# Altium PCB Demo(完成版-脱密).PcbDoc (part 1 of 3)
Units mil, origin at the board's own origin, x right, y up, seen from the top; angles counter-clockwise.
Board outline 2165.35 x 1574.8 mil, 6 copper layers (TOP, GND02, ART03, ART04, PWR05, BOTTOM); 172 components, 0 nets, 834 pads, 541 vias.
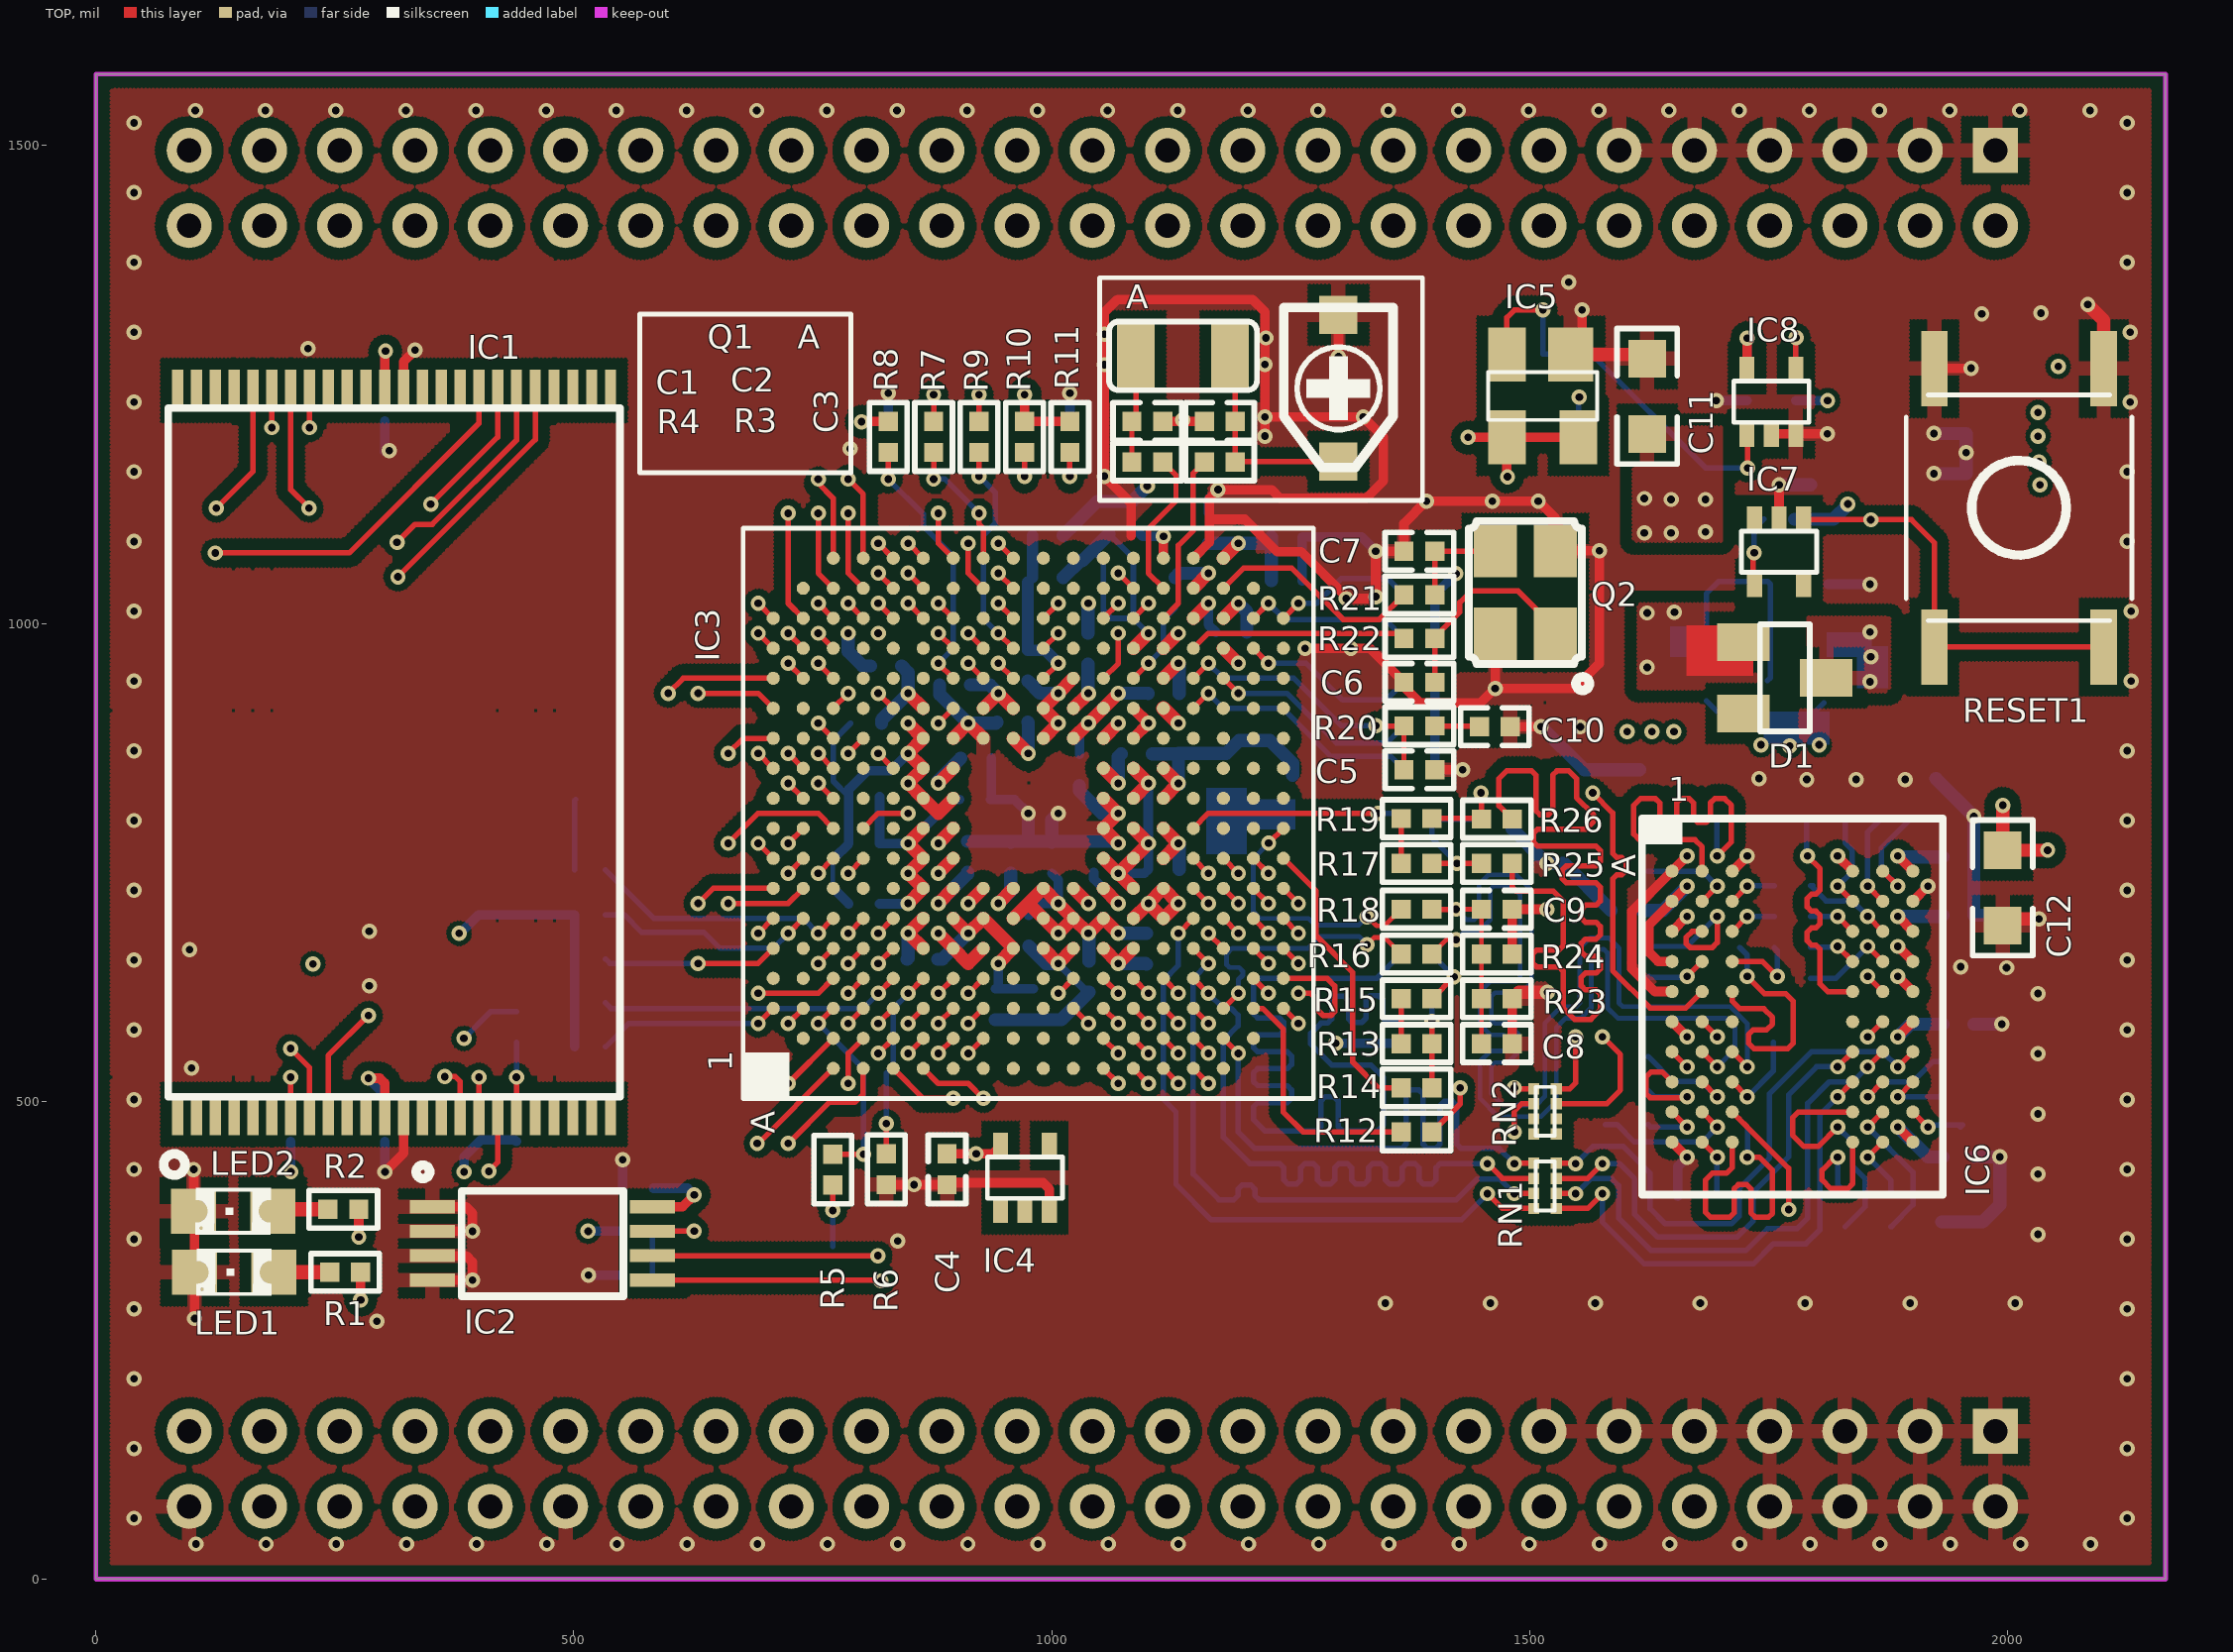
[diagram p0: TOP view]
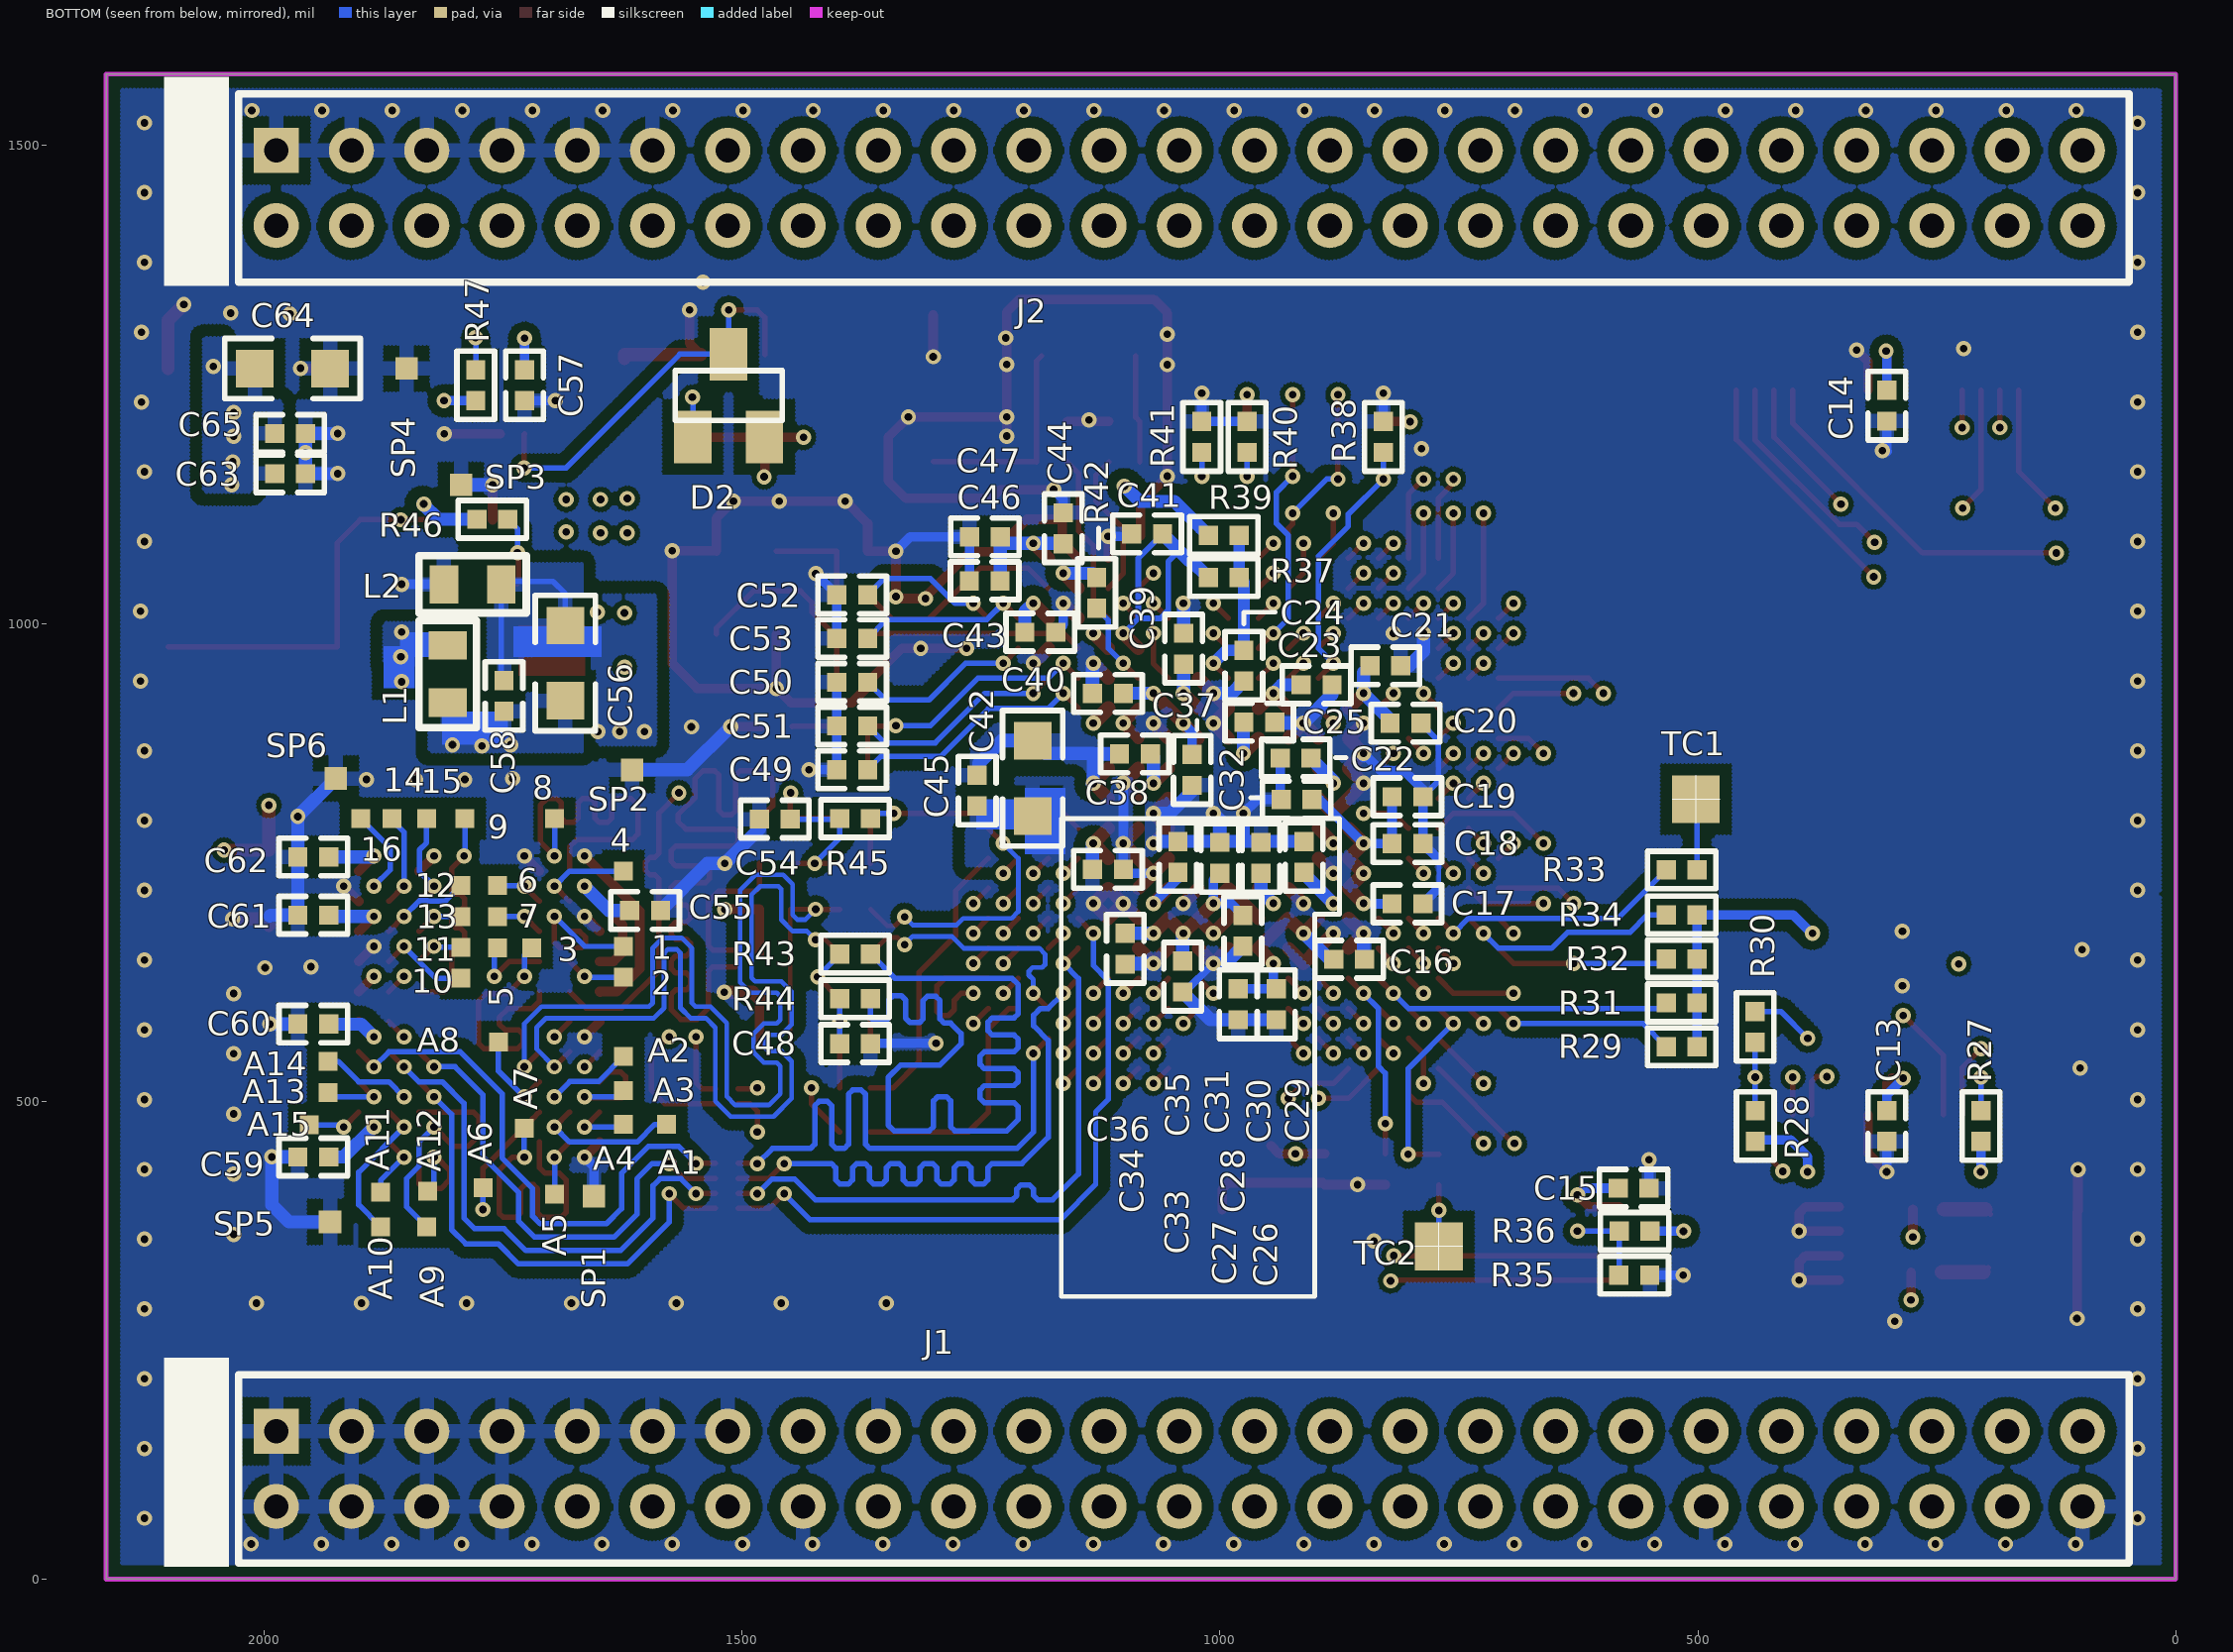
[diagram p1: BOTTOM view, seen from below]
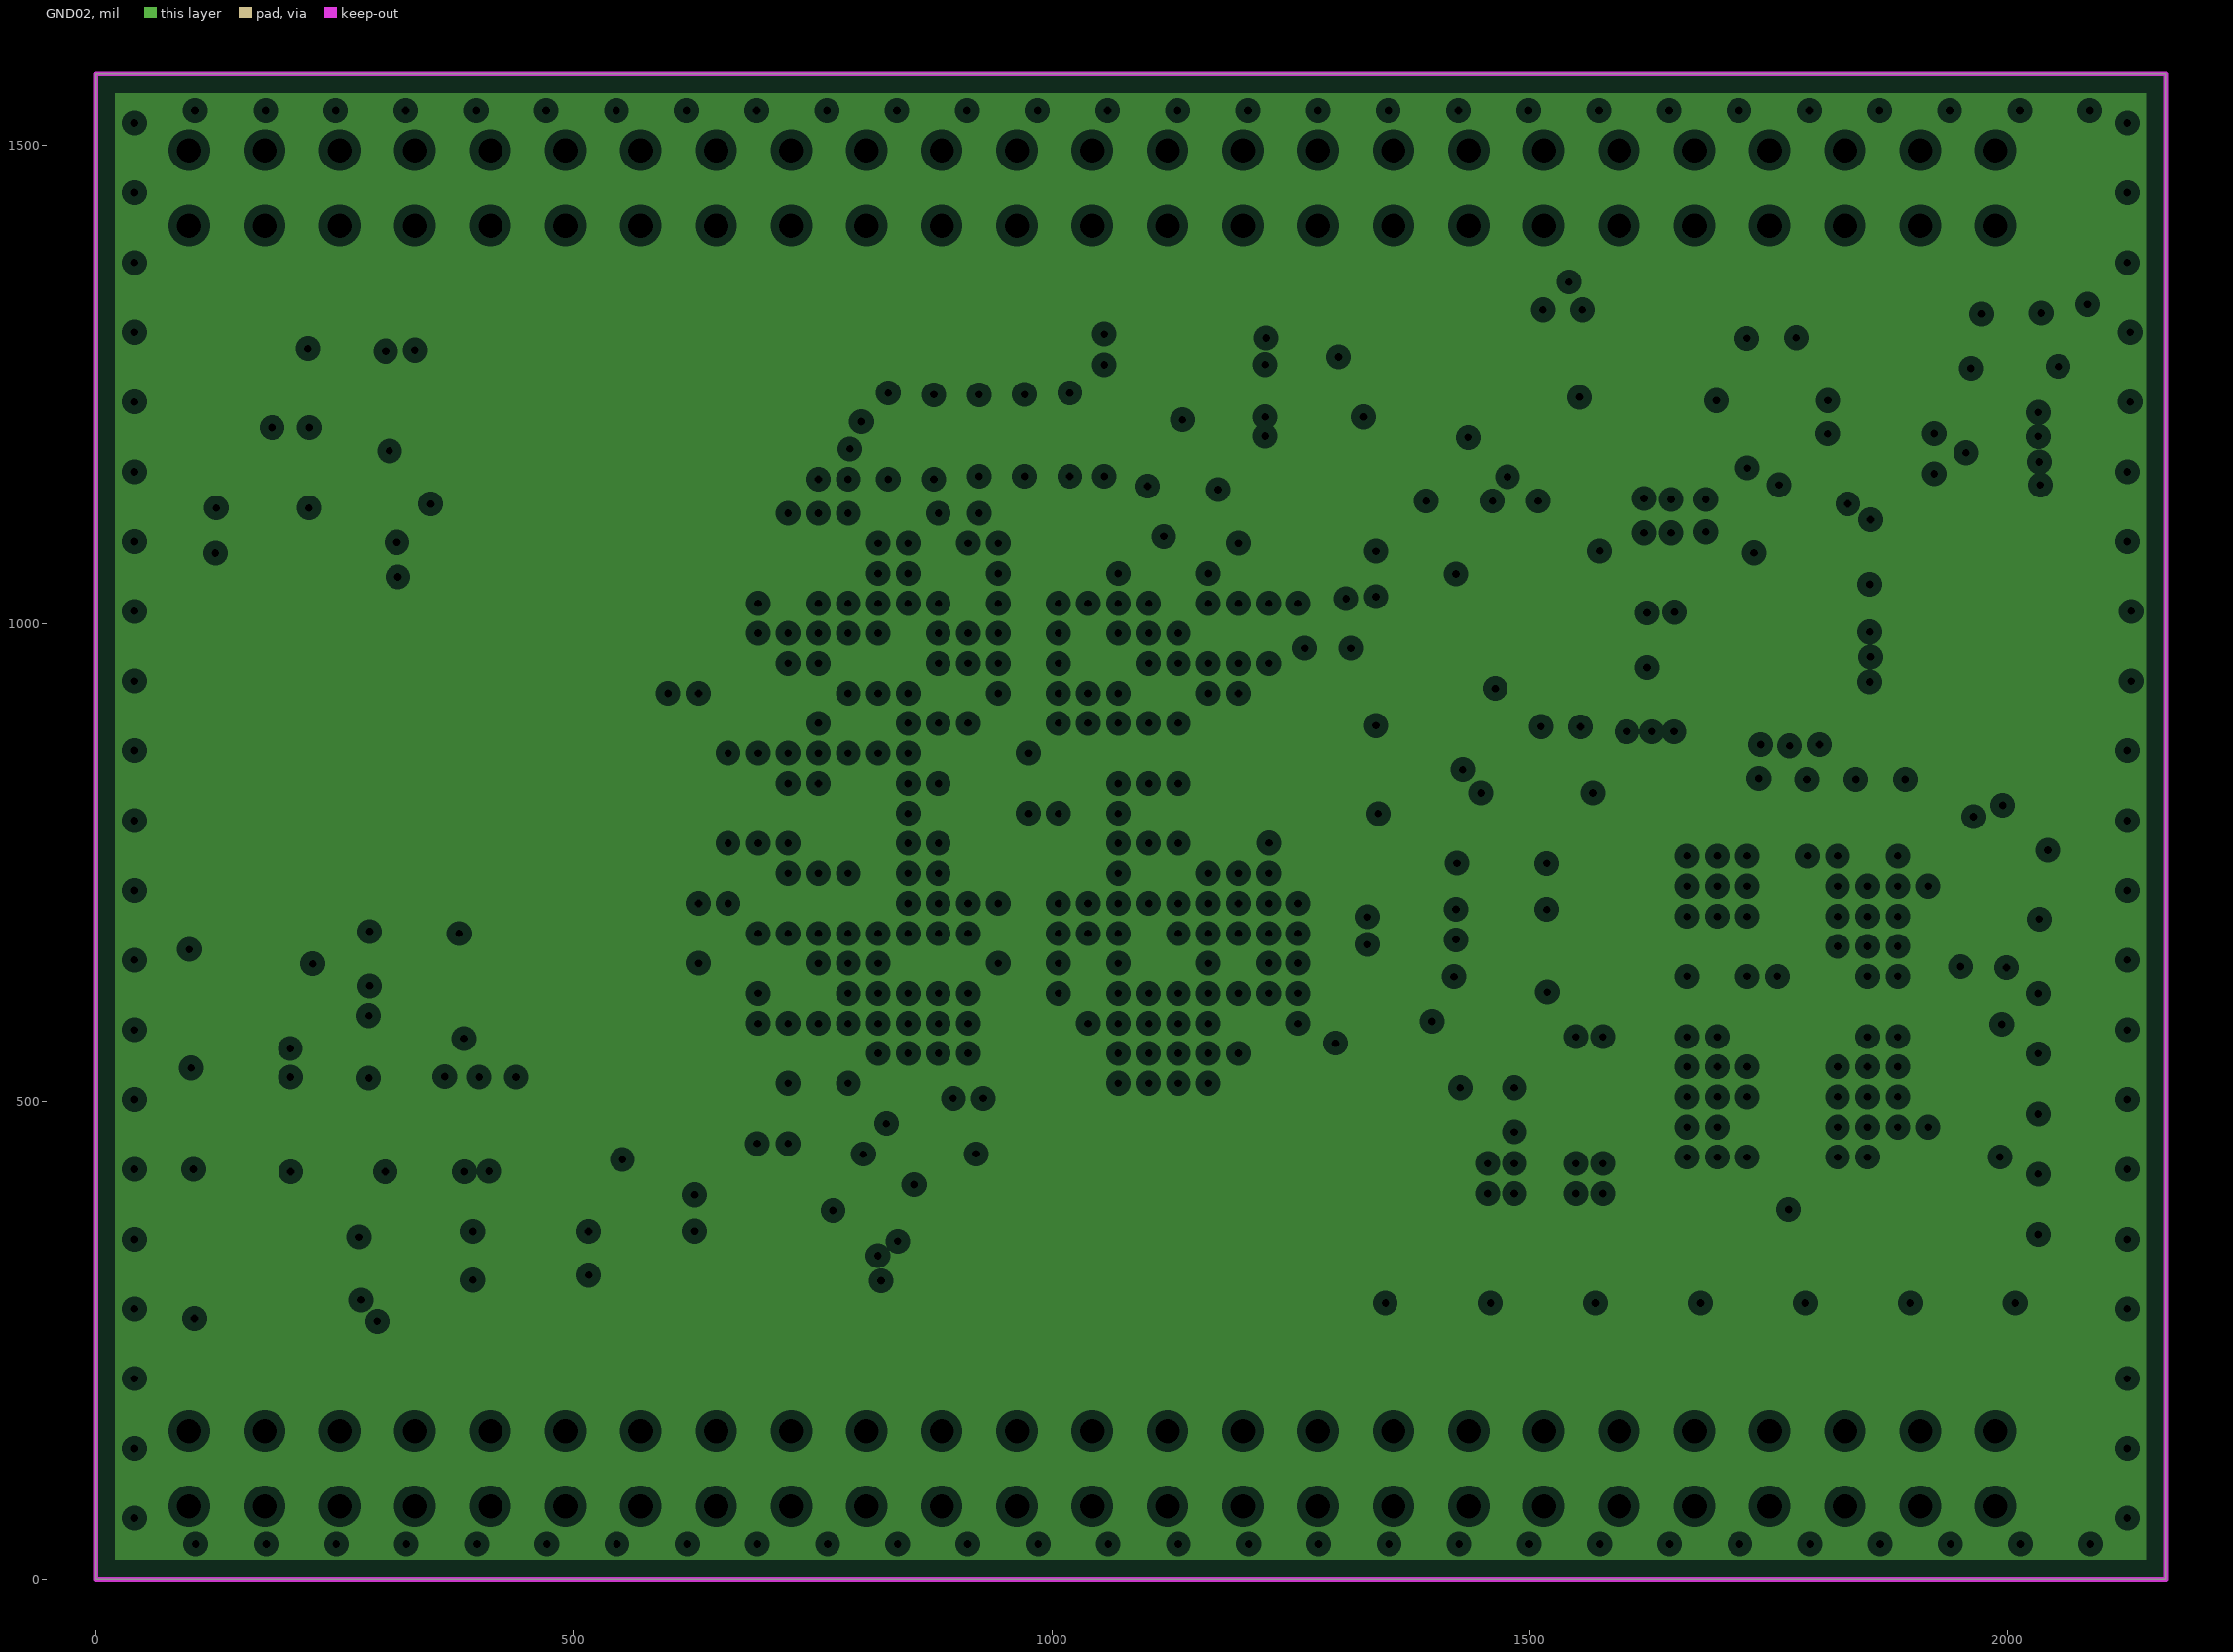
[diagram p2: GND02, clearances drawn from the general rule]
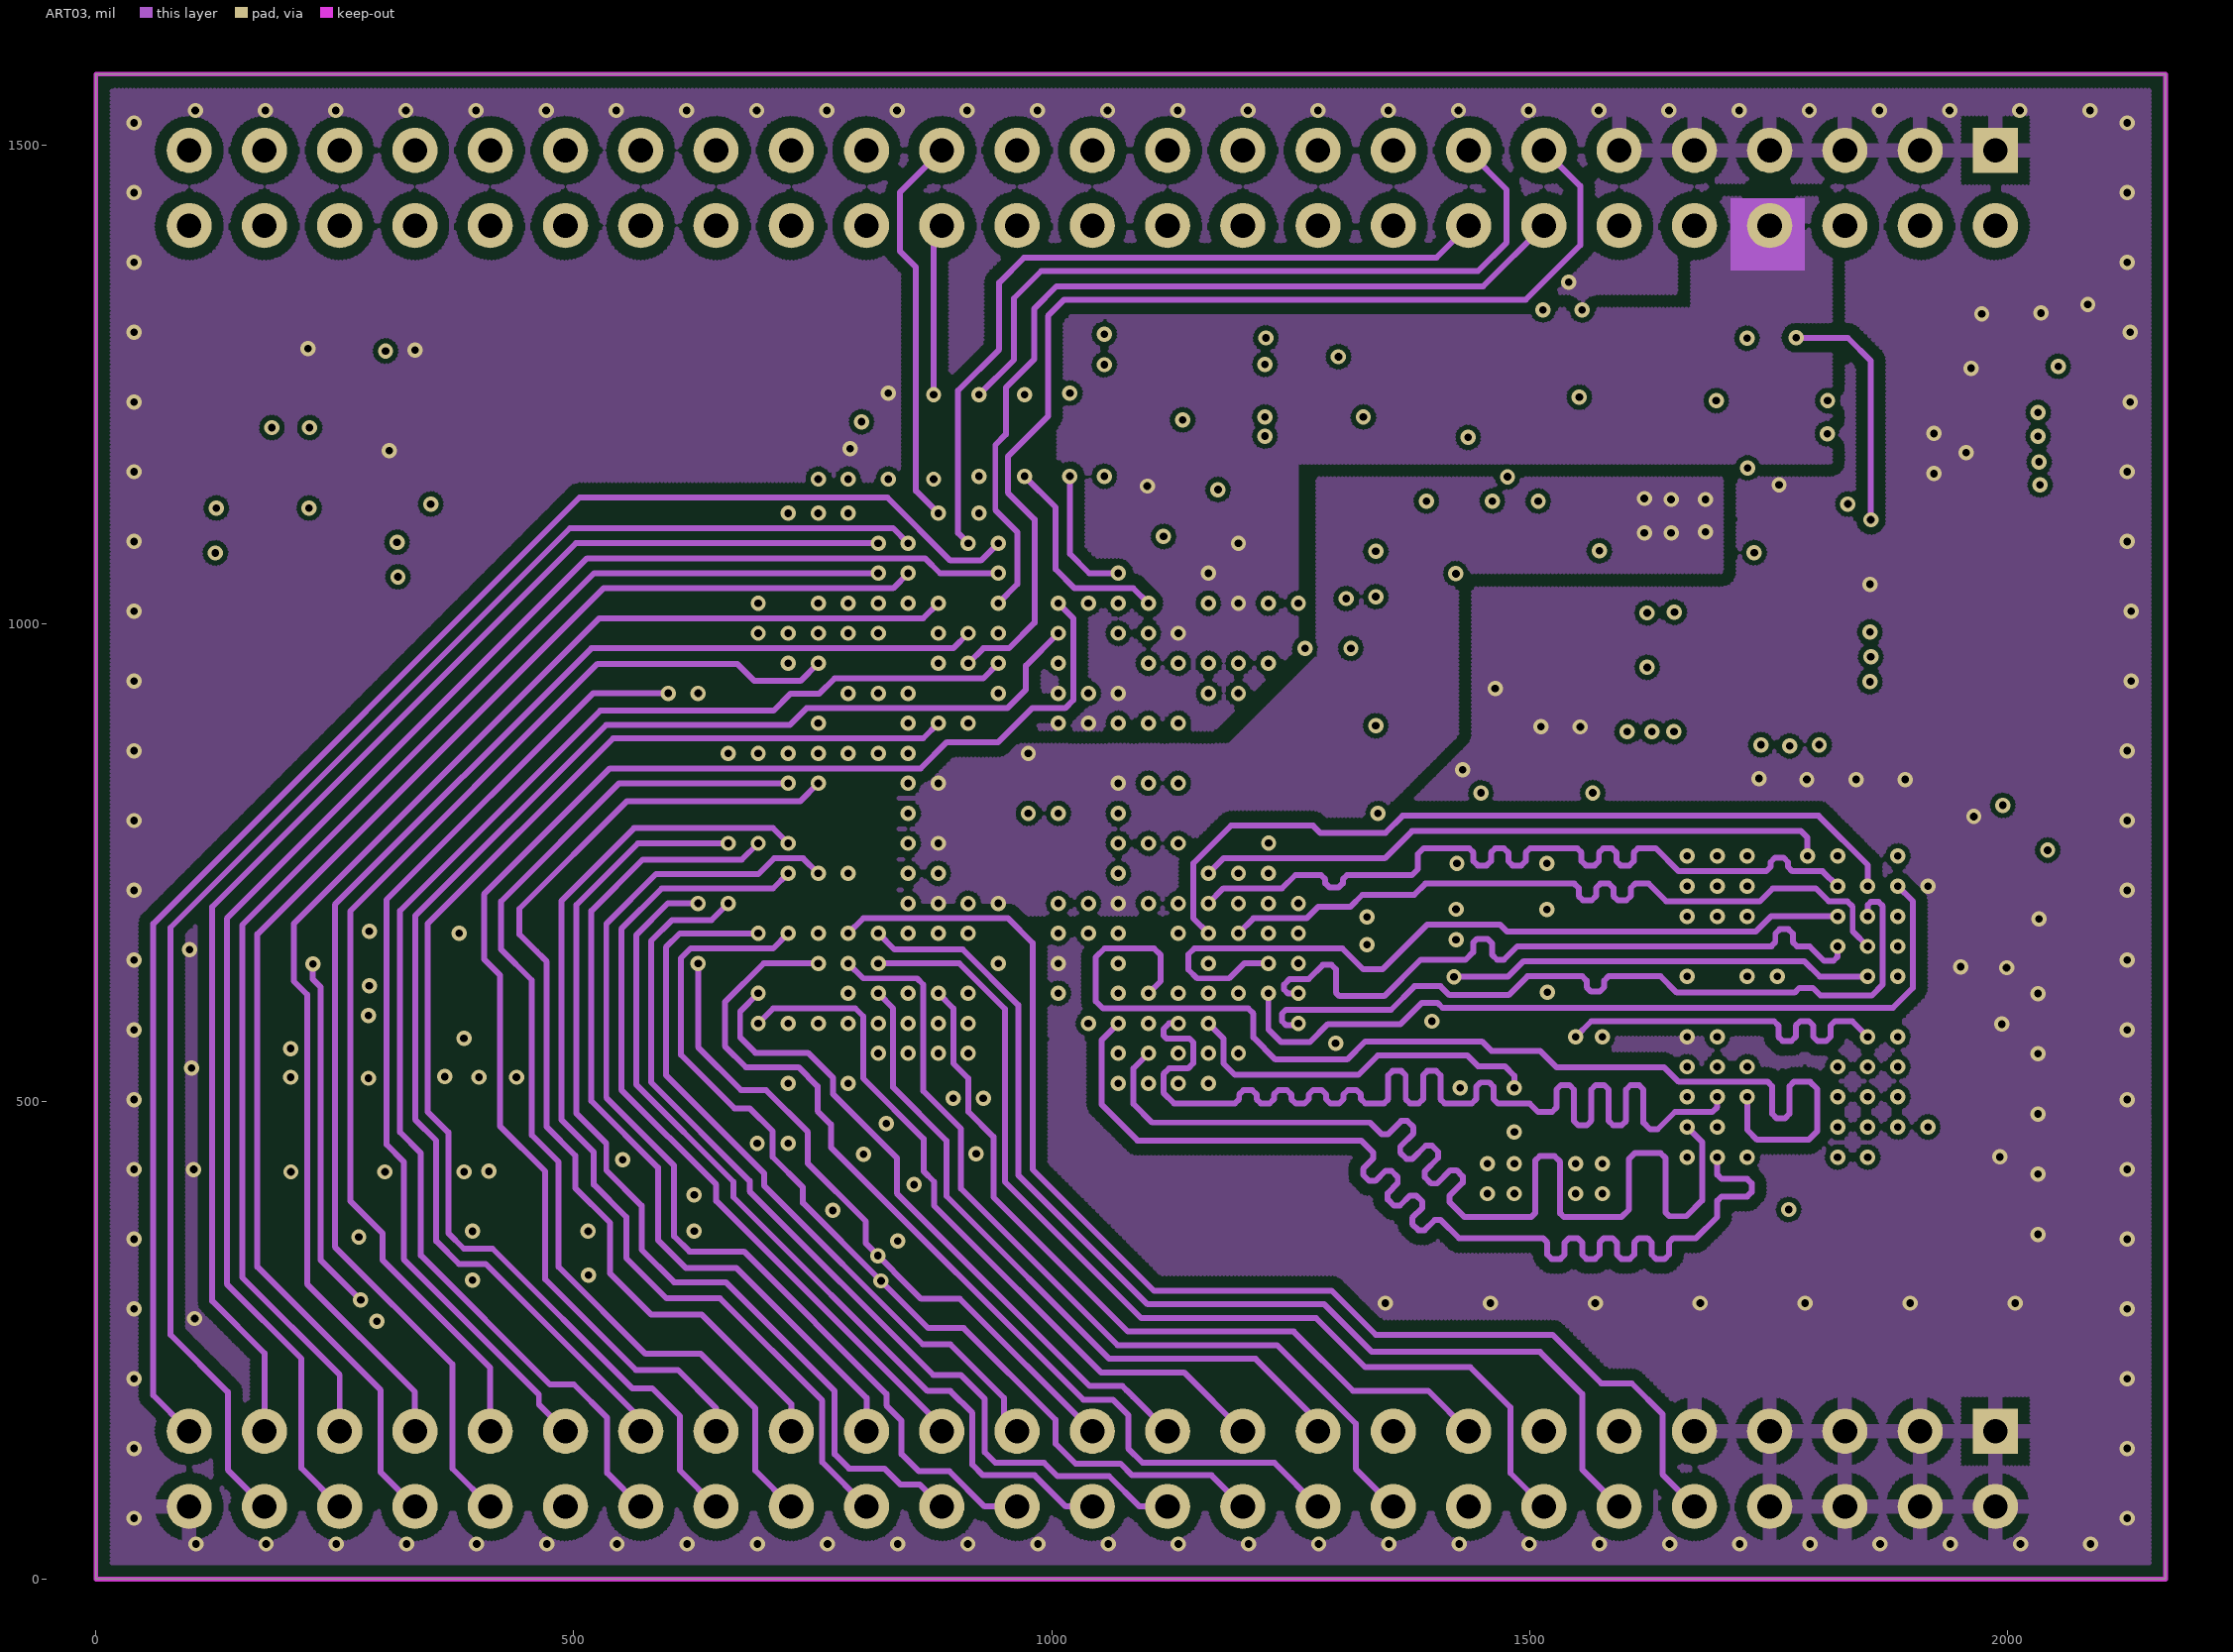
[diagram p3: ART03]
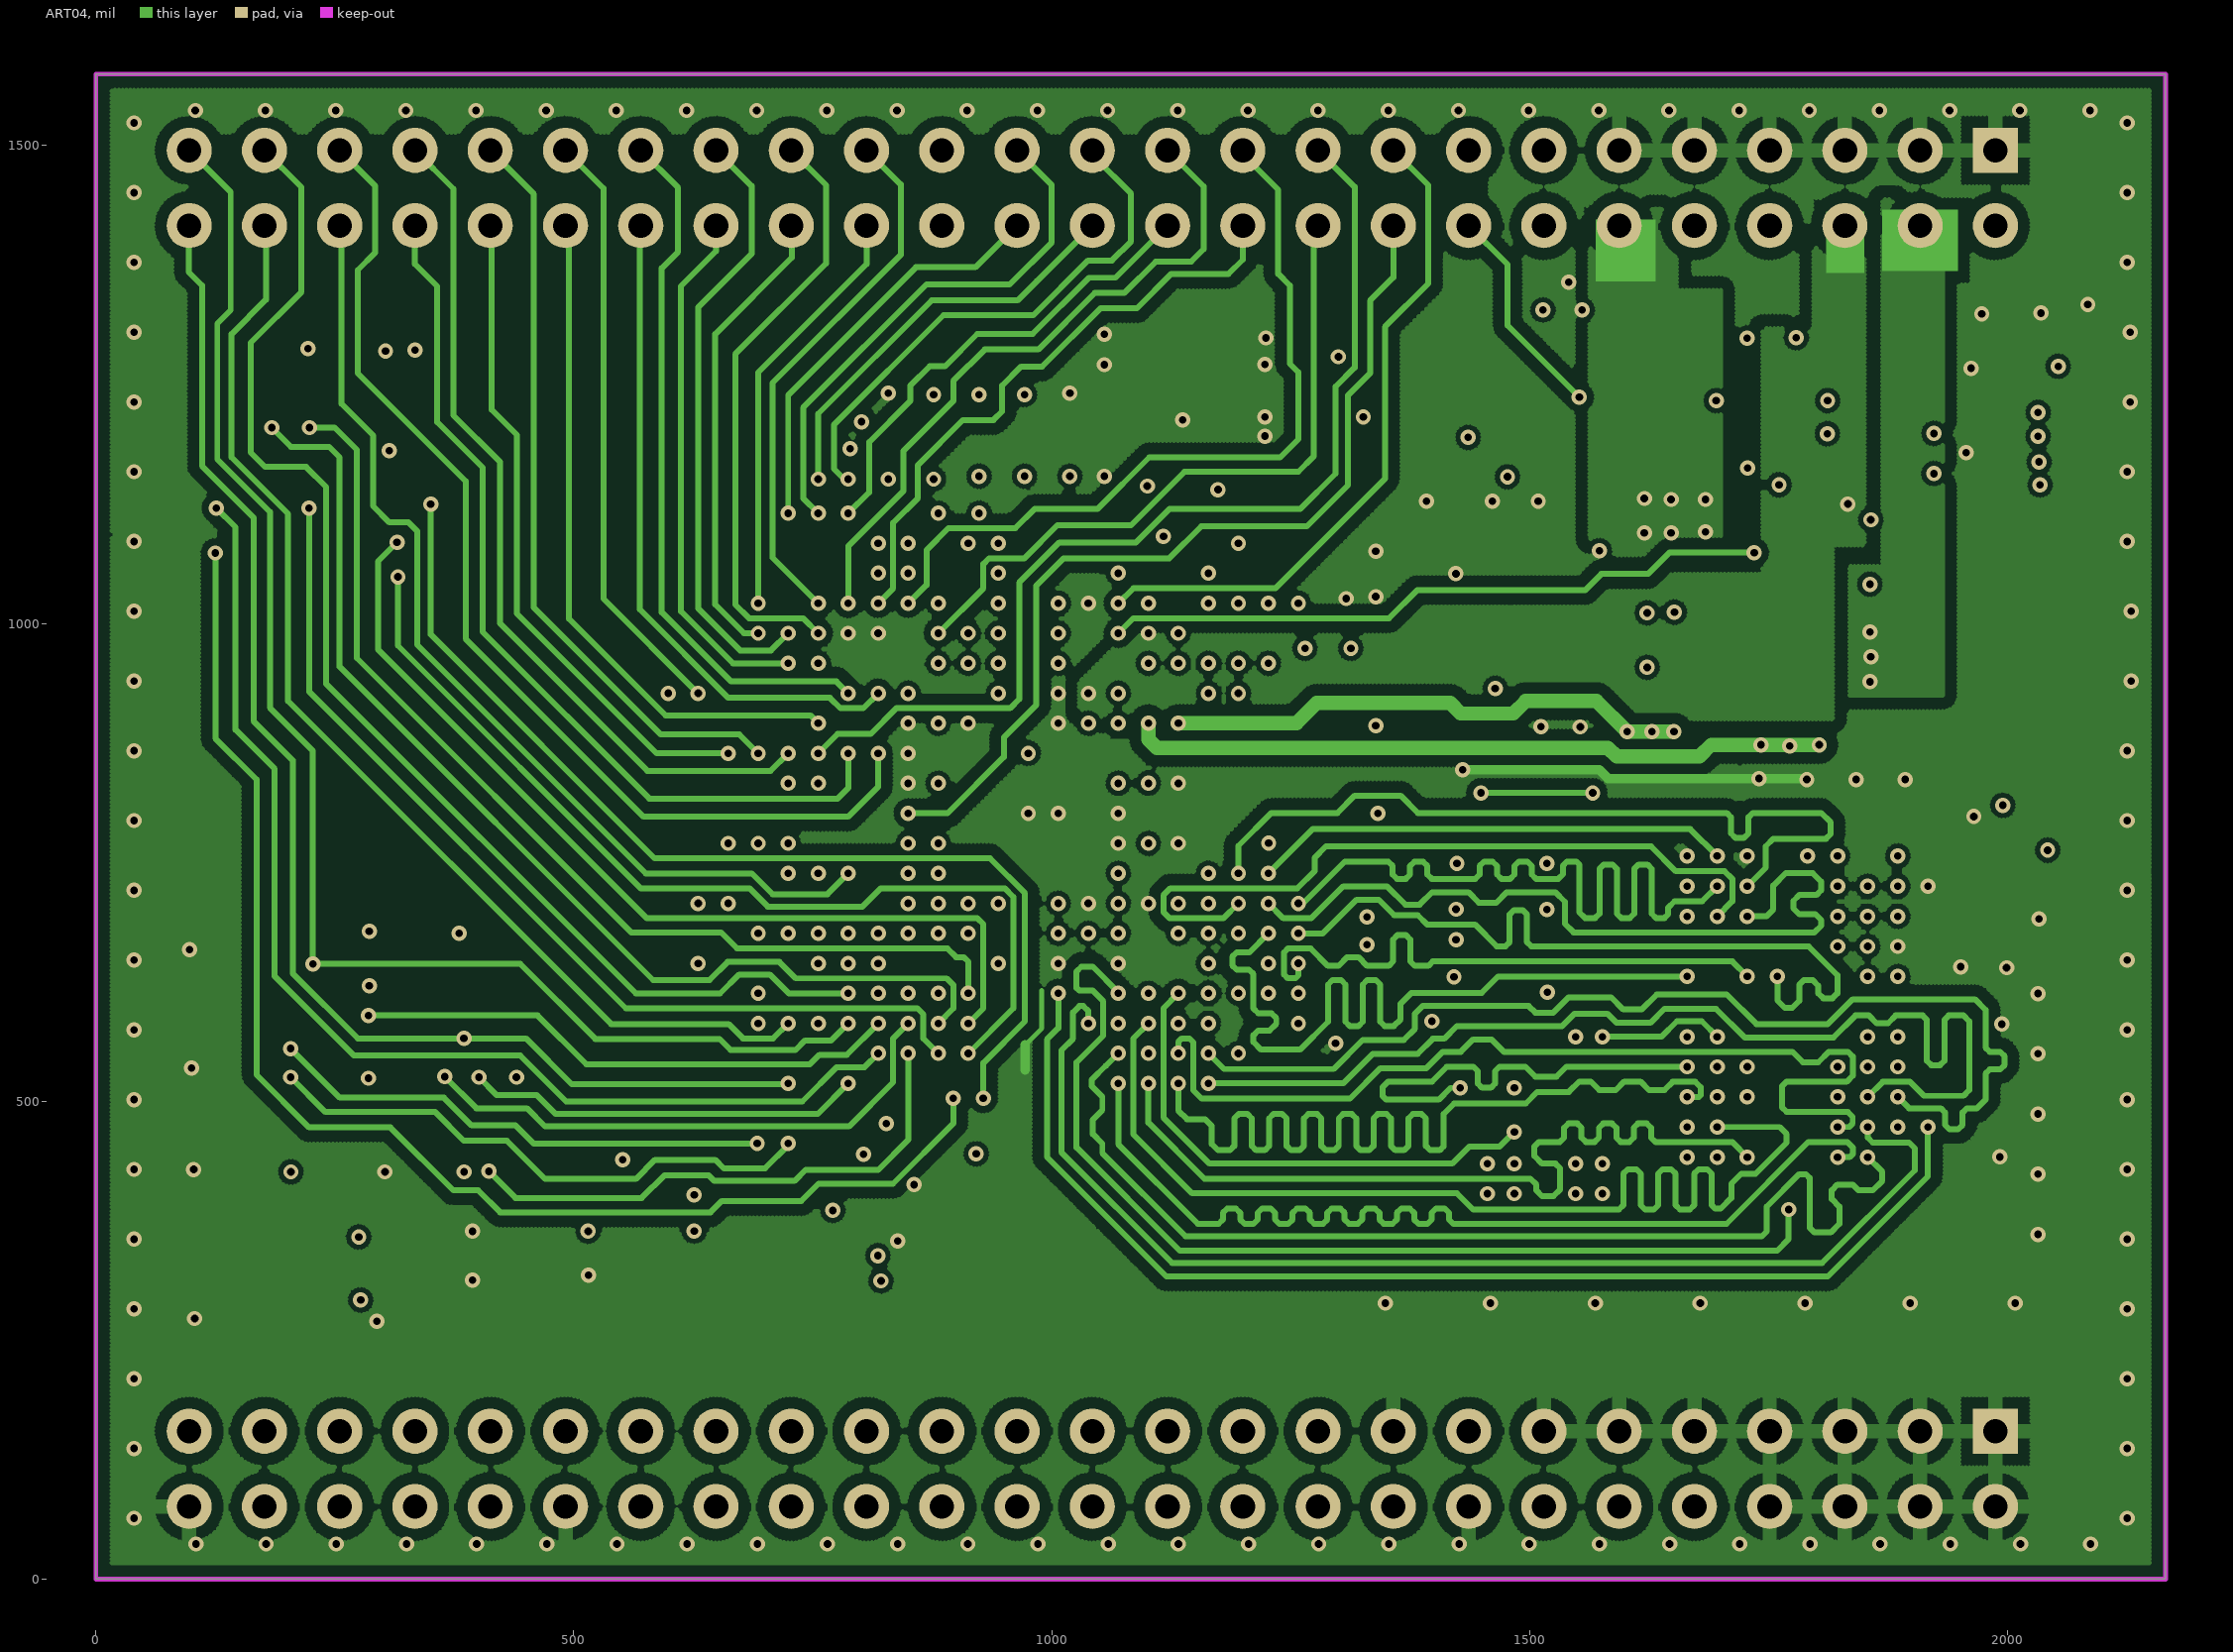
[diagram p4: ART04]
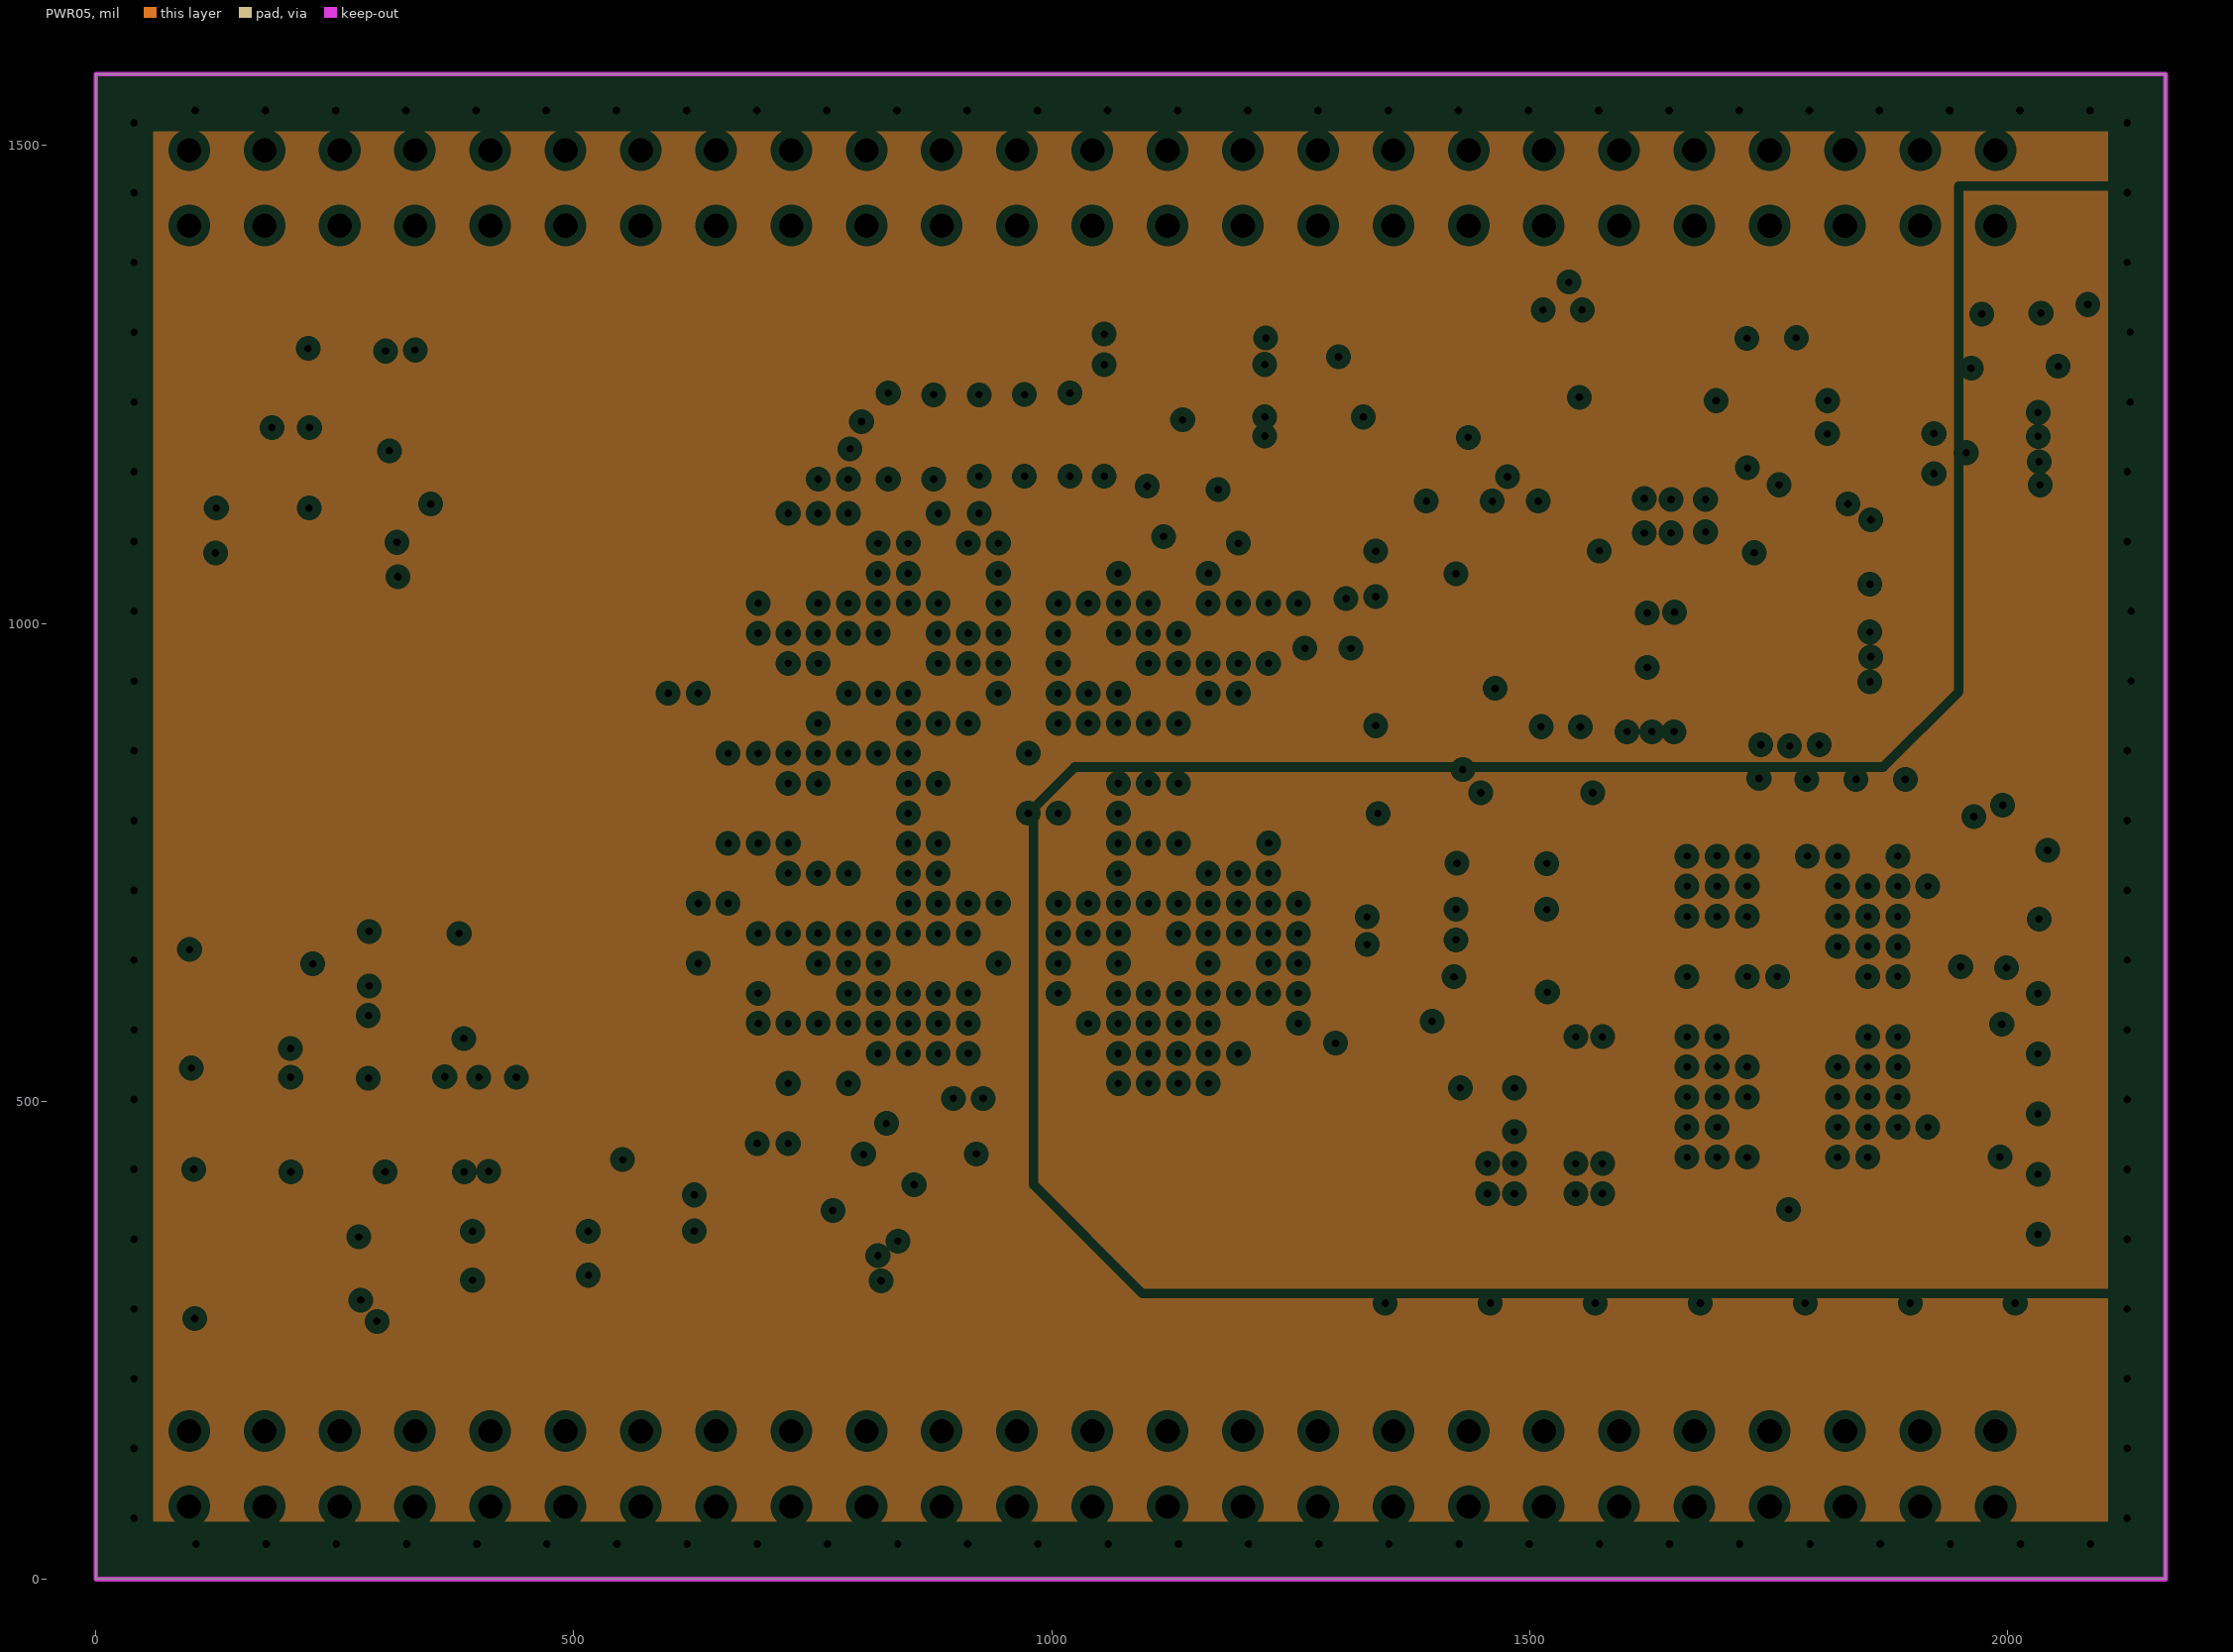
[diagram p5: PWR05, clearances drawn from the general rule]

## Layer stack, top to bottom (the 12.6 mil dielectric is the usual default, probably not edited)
TOP: signal copper 1.4
Dielectric: core 12.6, FR-4, Dk 4.8
GND02: plane copper 1.4
Dielectric: prepreg 12.6, FR-4, Dk 4.8
ART03: signal copper 1.4
Dielectric: core 12.6, FR-4, Dk 4.8
ART04: signal copper 1.4
Dielectric: prepreg 12.6, FR-4, Dk 4.8
PWR05: plane copper 1.4
Dielectric: core 12.6, FR-4, Dk 4.8
BOTTOM: signal copper 1.4

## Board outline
0,0 2165.35,0 2165.35,1574.8 0,1574.8

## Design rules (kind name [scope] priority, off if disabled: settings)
Clearance [ISVIA vs INPOLY] p1: gap=5
Clearance POLY-ALL [INPOLY] p2: gap=12
Clearance ALL [All] p3: gap=4.5
DiffPairsRouting DiffPair_100DiffPairsRouting [InDifferentialPairClass('100om')] p1: maxlimit=7 minlimit=7 mostfreqgap=7 maxuncoupledlength=500
MatchedLengths DiffPair_100MatchedLengths [InDifferentialPairClass('100om')] p1: tolerance=1000 checknetsindiffpair=TRUE checkdiffpairvsdiffpair=TRUE checkothers=TRUE
PlaneClearance [All] p1: clearance=9
PlaneConnect [All] p1: planeconnectstyle=Direct reliefexpansion=20 reliefentries=4 reliefconductorwidth=10 reliefairgap=10
PolygonConnect PolygonConnect_1 [ISVIA] p1: connectstyle=Direct reliefconductorwidth=10 reliefentries=4 polygonreliefangle="90 Angle"
PolygonConnect [All] p2: connectstyle=Relief reliefconductorwidth=15 reliefentries=4 polygonreliefangle="90 Angle"
RoutingVias [All] p1: holewidth=8 width=16 viastyle="Through Hole" minholewidth=8 minwidth=16 maxholewidth=8 maxwidth=16
SilkscreenOverComponentPads [All] p1: minsilkscreentomaskgap=10
SolderMaskExpansion [All] p1: expansion=2.5
Width DiffPair_100Width [(InDifferentialPairClass('100om'))] p1: maxlimit=5 minlimit=4.5 preferedwidth=5 toplayer_minwidth=5 midlayer1_maxwidth=4.5 midlayer1_prefwidth=4.5 midlayer2_maxwidth=4.5 midlayer2_prefwidth=4.5 bottomlayer_minwidth=5 minimp=50.000000 maximp=50.000000 favimp=50.000000
Width PWR [InNetClass('PWR')] p2: maxlimit=30 minlimit=10 preferedwidth=15
Width [All] p3: maxlimit=6.2 minlimit=5.7 preferedwidth=6.2 toplayer_maxwidth=5.7 toplayer_prefwidth=5.7 midlayer1_minwidth=6.2 midlayer2_minwidth=6.2 bottomlayer_maxwidth=5.7 bottomlayer_prefwidth=5.7 minimp=50.000000 maximp=50.000000 favimp=50.000000
24 further rules are at their usual default settings.

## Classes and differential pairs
differential pair class 100om: CLK DDR_CLK
net class GPIO: GPI_0 GPI_01/!SERVICE GPI_4 GPI_19/U4_RX GPIO_00 GPIO_01 GPIO_04/SSEL1/LCDVD22 GPO19/!WP_NAND! GPO_01 GPO_02 GPO_03 GPO_04 GPO_05 GPO_06/LCDVD(18) GPO_07/LCDVD(2) GPO_08/LCDVD(8) GPO_09/LCDVD(9) GPO_10/MCOB2 GPO_14 GPO_21/U4_TX/LCDVD(3) GPO_23/U2_HRTS/U3_RTS
component class "Reset,oscillators,JTAG Extensions LEDs,Buttons": C1 C2 C3 C4 C5 C6 C7 C10 C15 C49 C50 C51 C52 C53 C57 D2 IC2 IC3 IC4 IC5 IC7 IC8 LED1 LED2 Q1 Q2 R1 R2 R3 R4 R5 R6 R7 R8 R9 R10 R11 R20 R21 R22 R29 R31 R32 R33 R34 R35 R36 R38 R40 R41 R46 R47 R73 R74 RESET1 TC1 TC2
component class "Power supplies": C11 C16 C17 C18 C19 C20 C21 C22 C23 C24 C25 C26 C27 C28 C29 C30 C31 C32 C33 C34 C35 C36 C37 C38 C39 C40 C41 C42 C43 C44 C45 C46 C47 C56 C58 C63 C64 C65 D1 J1 J2 L1 L2 R37 R39 R42
component class "DDR RAM,NAND Flash": 1 2 3 4 5 6 7 8 9 10 11 12 13 14 15 16 A1 A2 A3 A4 A5 A6 A7 A8 A9 A10 A11 A12 A13 A14 A15 C8 C9 C12 C13 C14 C48 C54 C55 C59 C60 C61 C62 IC1 IC6 R12 R13 R14 R15 R16 R17 R18 R19 R23 R24 R25 R26 R27 R28 R30 R43 R44 R45 RN1 RN2 SP1 SP2 SP3 SP4 SP5 SP6
net class PWR: GND NetC41_1 NetC41_2 VDD_1V2 VDD_1V2_RTC VDD_1V2_VAR(1V33) VDD_3V3 VDD_EMC VDDA
net class I2C: I2C1_SCL I2C1_SDA I2C2_SCL I2C2_SDA
net class JTAG: JTAG_NTRST JTAG_RTCK JTAG_TCK JTAG_TDI JTAG_TDO JTAG_TMS
net class EN: EN_CRS EN_MDC EN_MDIO EN_RXCLK EN_RXD0 EN_RXD1 EN_RXDV EN_RXER EN_TXD0 EN_TXD1 EN_TXEN
net class ZZ: !SYS_RESET! !USB_ATX_INT! !USB_OE_TP! CD/DAT3 CLK CMD DAT0 DAT1 DAT2 EN_CRS EN_MDC EN_MDIO EN_RXCLK EN_RXD0 EN_RXD1 EN_RXDV EN_RXER EN_TXD0 EN_TXD1 EN_TXEN GPI_0 GPI_01/!SERVICE GPI_4 GPI_19/U4_RX GPIO_00 GPIO_01 GPIO_04/SSEL1/LCDVD22 GPO19/!WP_NAND! GPO_01 GPO_02 GPO_03 GPO_04 GPO_05 GPO_06/LCDVD(18) GPO_07/LCDVD(2) GPO_08/LCDVD(8) GPO_09/LCDVD(9) GPO_10/MCOB2 GPO_14 GPO_21/U4_TX/LCDVD(3) GPO_23/U2_HRTS/U3_RTS I2C1_SCL I2C1_SDA I2C2_SCL I2C2_SDA JTAG_NTRST JTAG_RTCK JTAG_TCK JTAG_TDI JTAG_TDO JTAG_TMS OVRCNT_B SPEED SPI1_CLK/SCK0 SPI1_DATIN/MISO0/GPI_25 SPI1_DATIO/MOSI0 SPI2_CLK/SCK1/LCDVD23 U1_RX/GPI_15 U1_TX U2_HCTS/U3_CTS/GPI_16 U3_RX/GPI_18 U3_TX U5_RX/GPI_20 U5_TX U6_IRRX/GPI_21 U6_IRTX U7_HCTS/CAP0.1 U7_RX/CAP0.0/LCDVD U7_TX/MAT1.1/LCDVD USB_DAT_VP USB_I2C_SCL USB_I2C_SDA USB_SE0_VM
net class DDRA: !CAS !DDR_CLK !RAS !WR ABUS0 ABUS1 ABUS2 ABUS3 ABUS4 ABUS5 ABUS6 ABUS7 ABUS8 ABUS9 ABUS10 ABUS11 ABUS12 ABUS13 ABUS14 DDR_CKE DDR_CLK DYCS0
net class D0-D7: CPU_DDR_DQS0 DBUS0 DBUS1 DBUS2 DBUS3 DBUS4 DBUS5 DBUS6 DBUS7 DDR_DSQ0 DQM0 NetIC7_V8
net class D8-D15: CPU_DDR_DQS1 DBUS8 DBUS9 DBUS10 DBUS11 DBUS12 DBUS13 DBUS14 DBUS15 DDR_DSQ1 DQM1 NetIC7_R9
differential pair CLK: +"" -""
differential pair DDR_CLK: +"" -""

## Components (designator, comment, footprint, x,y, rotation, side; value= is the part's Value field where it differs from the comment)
1 "*" B0,5MM 1624.01,662.04 r270 bottom (schematic designator 11)
2 "*" B0,5MM 1624.01,629.73 r180 bottom (schematic designator 9)
3 "*" B0,5MM 1720.01,660.73 r180 bottom (schematic designator 8)
4 "*" B0,5MM 1624.01,740.73 r270 bottom (schematic designator 13)
5 "*" B0,5MM 1756.01,660.73 r270 bottom (schematic designator 10)
6 "*" B0,5MM 1756.01,725.73 r270 bottom (schematic designator 14)
7 "*" B0,5MM 1756.01,693.4 r270 bottom (schematic designator 12)
8 "*" B0,5MM 1696.01,795.73 r180 bottom (schematic designator 15)
9 "*" B0,5MM 1790.01,795.73 r180 bottom (schematic designator 7)
10 "*" B0,5MM 1794.01,628.73 r180 bottom (schematic designator 6)
11 "*" B0,5MM 1794.01,661.06 r180 bottom (schematic designator 5)
12 "*" B0,5MM 1794.01,725.73 r180 bottom (schematic designator 4)
13 "*" B0,5MM 1794.01,693.4 r180 bottom (schematic designator 3)
14 "*" B0,5MM 1866.01,795.73 r180 bottom (schematic designator 2)
15 "*" B0,5MM 1830.01,795.73 r180 bottom (schematic designator 1)
16 "*" B0,5MM 1899.01,795.73 r180 bottom (schematic designator 0)
A1 "*" B0,5MM 1579.01,475.73 r270 bottom (schematic designator A7)
A2 "*" B0,5MM 1624.01,546.73 r180 bottom (schematic designator A11)
A3 "*" B0,5MM 1624.01,511.23 r270 bottom (schematic designator A9)
A4 "*" B0,5MM 1624.01,475.73 r180 bottom (schematic designator A6)
A5 "*" B0,5MM 1696.01,402.73 r270 bottom (schematic designator A4)
A6 "*" B0,5MM 1771.01,409.73 r180 bottom (schematic designator A8)
A7 "*" B0,5MM 1728.01,471.73 r270 bottom (schematic designator A5)
A8 "*" B0,5MM 1755.01,561.73 r180 bottom (schematic designator A12)
A9 "*" B0,5MM 1830.01,368.73 r180 bottom (schematic designator A10)
A10 "*" B0,5MM 1878.01,368.73 r270 bottom (schematic designator A0)
A11 "*" B0,5MM 1878.01,404.73 r270 bottom (schematic designator A3)
A12 "*" B0,5MM 1829.01,405.73 r270 bottom (schematic designator A2)
A13 "*" B0,5MM 1933.01,509.23 r180 bottom (schematic designator A14)
A14 "*" B0,5MM 1933.01,541.73 r180 bottom (schematic designator A13)
A15 "*" B0,5MM 1952.91,475.28 r270 bottom (schematic designator A1)
C1 "22p" 0402C 1100,1211.28 r180 top (schematic designator C63)
C2 "22p" 0402C 1176,1211.28 r0 top (schematic designator C62)
C3 "5-20p" CTRIMCTZ3 1300,1246 r180 top (schematic designator C20)
C4 "100n" 0402C 890.49,428.86 r270 top (schematic designator C66)
C5 "150p" 0402C 1384.64,847 r0 top (schematic designator C65)
C6 "22p" 0402C 1384.64,938.45 r0 top (schematic designator C61)
C7 "22p" 0402C 1384.64,1075.62 r0 top (schematic designator C60)
C8 "na" 0402C 1465.7,560.34 r0 top (schematic designator C76)
C9 "na" 0402C 1465.7,700.91 r180 top (schematic designator C77)
C10 "3n9" 0402C 1463.7,892 r180 top (schematic designator C64)
C11 "10u/X7R" 0805C 1623.01,1237.63 r90 top (schematic designator C38)
C12 "10u/X7R" 0805C 1995.01,723.36 r270 top (schematic designator C83)
C13 "100n" 0402C 302.16,474 r270 bottom (schematic designator C68)
C14 "10n" 0402C 302.16,1227.8 r270 bottom (schematic designator C67)
C15 "100n" 0402C 567.17,409 r0 bottom (schematic designator C9)
C16 "100n" 0402C 864.86,648.6 r180 bottom (schematic designator C59)
C17 "100n" 0402C 803.86,706.6 r180 bottom (schematic designator C57)
C18 "10n" 0402C 803.86,769.6 r180 bottom (schematic designator C58)
C19 "100n" 0402C 803.86,818.6 r180 bottom (schematic designator C55)
C20 "10n" 0402C 805.86,895.6 r180 bottom (schematic designator C54)
C21 "100n" 0402C 826.86,955.6 r180 bottom (schematic designator C51)
C22 "10n" 0402C 920.83,859 r0 bottom (schematic designator C31)
C23 "10n" 0402C 898.87,935.73 r180 bottom (schematic designator C52)
C24 "100n" 0402C 975.01,955.73 r270 bottom (schematic designator C45)
C25 "100n" 0402C 958.87,896.73 r180 bottom (schematic designator C36)
C26 "10n" 0402C 941,601.46 r270 bottom (schematic designator C56)
C27 "100n" 0402C 981,601.46 r270 bottom (schematic designator C53)
C28 "10n" 0402C 976,678.46 r270 bottom (schematic designator C18)
C29 "100n" 0402C 912,755.74 r90 bottom (schematic designator C35)
C30 "10n" 0402C 957,754.74 r90 bottom (schematic designator C33)
C31 "10n" 0402C 1000,754.74 r90 bottom (schematic designator C12)
C32 "10n" 0402C 919.86,815.6 r0 bottom (schematic designator C50)
C33 "10n" 0402C 1039,630.46 r270 bottom (schematic designator C17)
C34 "100n" 0402C 1099.01,659.59 r270 bottom (schematic designator C13)
C35 "100n" 0402C 1044,755.74 r90 bottom (schematic designator C37)
C36 "100n" 0402C 1117.14,742.6 r0 bottom (schematic designator C29)
C37 "100n" 0402C 1029,846.74 r270 bottom (schematic designator C40)
C38 "10n" 0402C 1089,863.6 r0 bottom (schematic designator C32)
C39 "100n" 0402C 1038,973.6 r90 bottom (schematic designator C43)
C40 "10n" 0402C 1117.14,926.6 r0 bottom (schematic designator C39)
C41 "100n" 0402C 1076.15,1093.73 r0 bottom (schematic designator C44)
C42 "10u/X7R" 0805C 1196,838 r90 bottom (schematic designator C14)
C43 "100n" 0402C 1188,990.73 r180 bottom (schematic designator C48)
C44 "100n" 0402C 1164,1099.6 r90 bottom (schematic designator C49)
C45 "100n" 0402C 1254,825 r90 bottom (schematic designator C25)
C46 "100n" 0402C 1246.14,1044.6 r0 bottom (schematic designator C47)
C47 "100n" 0402C 1245.86,1090.6 r0 bottom (schematic designator C46)
C48 "na" 0402C 1381.7,560.34 r180 bottom (schematic designator C75)
C49 "1n" 0402C 1384.64,847 r0 bottom (schematic designator C70)
C50 "1n" 0402C 1384.64,938.45 r0 bottom (schematic designator C73)
C51 "1n" 0402C 1384.64,892.72 r0 bottom (schematic designator C72)
C52 "1n" 0402C 1384.64,1029.9 r0 bottom (schematic designator C71)
C53 "1n" 0402C 1384.64,984.17 r0 bottom (schematic designator C69)
C54 "na" 0402C 1465.7,795.23 r0 bottom (schematic designator C74)
C55 "100n" 0402C 1601.38,699.73 r180 bottom (schematic designator C82)
C56 "10u/X7R" 0805C 1685,958.37 r90 bottom (schematic designator C42)
C57 "100n" 0402C 1727.41,1249.32 r90 bottom (schematic designator C1)
C58 "10n" 0402C 1749,924.14 r90 bottom (schematic designator C41)
C59 "10n" 0402C 1948.62,441.73 r0 bottom (schematic designator C79)
C60 "100n" 0402C 1948.62,580.73 r0 bottom (schematic designator C80)
C61 "100n" 0402C 1948.62,694.73 r0 bottom (schematic designator C81)
C62 "10n" 0402C 1948.62,755.73 r0 bottom (schematic designator C78)
C63 "10n" 0402C 1972.87,1156.73 r180 bottom (schematic designator C15)
C64 "10u/X7R" 0805C 1970.38,1266.67 r180 bottom (schematic designator C30)
C65 "100n" 0402C 1972.87,1198.73 r180 bottom (schematic designator C16)
D1 "BAT754" SOT23 1767,943 r270 top
D2 "BAT754" SOT23 1514,1238.38 r180 bottom (schematic designator D10)
IC1 "*" TSOP48 312,865 r90 top (schematic designator IC9)
IC2 "24LC256-I/ST" TSSOP8 467.15,351.2 r270 top (schematic designator IC4)
IC3 "*" SOT1048-1 975.51,801.3 r90 top (schematic designator IC7)
IC4 "" SC70-5 972,420 r0 top (schematic designator IC8P)
IC5 "*" SOT143 1513.6,1238 r0 top (schematic designator IC1)
IC6 "H5MS5162EFR" FBGA60-6X10 1775,599.06 r0 top (schematic designator IC10)
IC7 "74LVC1G125GW" SC70-5 1761,1075 r180 top (schematic designator IC8)
IC8 "74LVC1G125GW" SC70-5 1753,1232 r0 top (schematic designator IC2)
J1 "LPC3240 Head P1" "LPC3240 HEAD" 1987.36,154.74 r180 bottom (schematic designator J2)
J2 "LPC3240 Head P1" "LPC3240 HEAD" 1987.36,1495 r180 bottom (schematic designator J1)
L1 "BLM18AG221SN1D" 0603R 1808.01,977 r270 bottom
L2 "BLM18AG221SN1D" 0603R 1811.91,1041 r180 bottom
LED1 "OVS-0806(Y)" CHIPLED_0805 144.66,321 r90 top (schematic designator LED2)
LED2 "OVS-0803(B)" CHIPLED_0805 143.66,385 r90 top (schematic designator LED1)
Q1 "32.768kHz" XTAL2 1135,1280 r0 top (schematic designator Q4)
Q2 "12MHz" XTAL4 1495.51,1052 r90 top (schematic designator Q5)
R1 "470E" 0402R 260.86,321 r0 top (schematic designator R3)
R2 "150E" 0402R 258.86,387 r0 top
R3 "0E" 0402R 1176,1169 r180 top (schematic designator R52)
R4 "0E" 0402R 1100,1169 r0 top (schematic designator R49)
R5 "22E" 0402R 771,428.46 r270 top (schematic designator R112)
R6 "33k" 0402R 827,428.86 r90 top (schematic designator R105)
R7 "22E" 0402R 876.5,1195.14 r90 top (schematic designator R110)
R8 "na (0E for boundary scan)" 0402R 829,1195.14 r270 top (schematic designator R12)
R9 "22E" 0402R 924,1195.14 r90 top (schematic designator R111)
R10 "na" 0402R 971.5,1195.14 r90 top (schematic designator R108)
R11 "33k" 0402R 1019,1195.14 r90 top (schematic designator R109)
R12 "0E" 0402R 1381.7,467.88 r0 top (schematic designator R89)
R13 "na" 0402R 1381.7,560.34 r180 top (schematic designator R86)
R14 "0E" 0402R 1381.7,513.88 r0 top (schematic designator R26)
R15 "na" 0402R 1381.7,607.2 r0 top (schematic designator R38)
R16 "22E" 0402R 1381.7,654.06 r0 top (schematic designator R33)
R17 "na" 0402R 1381.7,748.97 r180 top (schematic designator R87)
R18 "na" 0402R 1381.7,700.91 r0 top (schematic designator R32)
R19 "na" 0402R 1381.7,795.83 r0 top (schematic designator R39)
R20 "120k" 0402R 1384.64,892.72 r180 top (schematic designator R55)
R21 "0E" 0402R 1384.64,1029.9 r180 top (schematic designator R54)
R22 "0E" 0402R 1384.64,984.17 r180 top (schematic designator R53)
R23 "4k7" 0402R 1465.7,607.2 r180 top (schematic designator R81)
R24 "4k7" 0402R 1465.7,654.06 r0 top (schematic designator R80)
R25 "0E" 0402R 1465.7,748.97 r180 top (schematic designator R84)
R26 "22E" 0402R 1465.7,795.23 r180 top (schematic designator R85)
R27 "2k2" 0402R 203.73,474 r270 bottom (schematic designator R58)
R28 "33k" 0402R 439.95,474 r270 bottom (schematic designator R78)
R29 "3k3" 0402R 516.86,557 r180 bottom (schematic designator R73)
R30 "0E" 0402R 440.01,577.73 r270 bottom (schematic designator R79)
R31 "3k3" 0402R 516.86,603 r180 bottom (schematic designator R74)
R32 "3k3" 0402R 516.86,649 r180 bottom (schematic designator R71)
R33 "22E" 0402R 516.86,742 r180 bottom (schematic designator R113)
R34 "3k3" 0402R 516.86,695 r180 bottom (schematic designator R72)
R35 "10k" 0402R 566.45,318 r0 bottom (schematic designator R130)
R36 "na" 0402R 566.17,364 r180 bottom (schematic designator R129)
R37 "0E" 0402R 996,1048 r0 bottom (schematic designator R48)
R38 "10k" 0402R 829,1195.14 r270 bottom (schematic designator R135)
R39 "na" 0402R 996,1092 r0 bottom (schematic designator R47)
R40 "33k" 0402R 971.5,1195.14 r270 bottom (schematic designator R106)
R41 "na" 0402R 1019,1195.14 r270 bottom (schematic designator R107)
R42 "0E" 0402R 1129,1032 r90 bottom (schematic designator R46)
R43 "22E" 0402R 1381.7,654.06 r0 bottom (schematic designator R83)
R44 "0E" 0402R 1381.7,607.2 r0 bottom (schematic designator R82)
R45 "0E" 0402R 1381.7,795.83 r0 bottom (schematic designator R31)
R46 "10k" 0402R 1761.14,1109 r0 bottom (schematic designator R56)
R47 "33k" 0402R 1778.59,1249.32 r270 bottom (schematic designator R1)
RESET1 "MCDTSA6-2K" SMD-KEY 2012,1121 r270 top (schematic designator RESET)
RN1 "22E" EXB18V 1516.15,411.44 r270 top (schematic designator RN10)
RN2 "22E" EXB18V 1516.15,489.44 r270 top (schematic designator RN9)
SP1 "*" TP06SQ 1655.01,400.73 r180 bottom (schematic designator SP24)
SP2 "*" TP06SQ 1615.01,846.73 r180 bottom (schematic designator SP25)
SP3 "*" TP06SQ 1794.01,1145 r180 bottom (schematic designator SP21)
SP4 "*" TP06SQ 1851.01,1266.73 r180 bottom (schematic designator SP26)
SP5 "*" TP06SQ 1931.01,373.73 r180 bottom (schematic designator SP23)
SP6 "*" TP06SQ 1925.01,837.73 r180 bottom (schematic designator SP22)
TC1 "*" B1,27 502,816 r180 bottom (schematic designator TC2)
TC2 "*" B1,27 771,348 r180 bottom (schematic designator TC1)

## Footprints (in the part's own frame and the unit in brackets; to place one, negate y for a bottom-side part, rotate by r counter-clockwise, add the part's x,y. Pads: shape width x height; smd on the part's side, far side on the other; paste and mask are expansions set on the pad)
0402C [mm]
  rect 0.51x0.51 smd: 1(-0.41,0) 2(0.41,0)
  silkscreen extent -0.91,-0.5 0.91,0.5
0402R [mm]
  rect 0.51x0.51 smd: 1(-0.41,0) 2(0.41,0)
  silkscreen extent -0.91,-0.5 0.91,0.5
0603R [mil]
  rect 30x40 smd: 1(0.01,0.01) 2(60.01,0.01)
  silkscreen extent -26,-30 86,30
0805C [mm]
  rect 1x1 smd: 1(-1,0) 2(1,0)
  silkscreen extent -1.8,-0.8 1.8,0.8
B0,5MM [mm]
  rect 0.5x0.5 smd: TP(0,0)
B1,27 [mil]
  rect 50x50 smd: TP(0,0)
  silkscreen extent -25,-25 25,25
CHIPLED_0805 [mm]
  rect 1.2x1.2 smd: A(0,-1.05) C(0,1.05)
  silkscreen extent -0.62,-1 0.62,1.01
CTRIMCTZ3 [mil]
  rect 40x40 smd: 1(0,76.77) 2(0,-76.77)
  silkscreen extent -57,-85 57,83
EXB18V [mm]
  rect 0.3x0.3 smd: 1(-0.6,-0.3) 2(-0.2,-0.3) 3(0.2,-0.3) 4(0.6,-0.3) 5(0.6,0.3) 6(0.2,0.3) 7(-0.2,0.3) 8(-0.6,0.3)
  silkscreen extent -0.65,-0.25 0.65,0.25
FBGA60-6X10 [mm]
  round 0.35 smd: A1(-3.2,3.6) A2(-2.4,3.6) A3(-1.6,3.6) A7(1.6,3.6) A8(2.4,3.6) A9(3.2,3.6) B1(-3.2,2.8) B2(-2.4,2.8) B3(-1.6,2.8) B7(1.6,2.8) B8(2.4,2.8) B9(3.2,2.8) C1(-3.2,2) C2(-2.4,2) C3(-1.6,2) C7(1.6,2) C8(2.4,2) C9(3.2,2) D1(-3.2,1.2) D2(-2.4,1.2) D3(-1.6,1.2) D7(1.6,1.2) D8(2.4,1.2) D9(3.2,1.2) E1(-3.2,0.4) E2(-2.4,0.4) E3(-1.6,0.4) E7(1.6,0.4) E8(2.4,0.4) E9(3.2,0.4) F1(-3.2,-0.4) F2(-2.4,-0.4) F3(-1.6,-0.4) F7(1.6,-0.4) F8(2.4,-0.4) F9(3.2,-0.4) G1(-3.2,-1.2) G2(-2.4,-1.2) G3(-1.6,-1.2) G7(1.6,-1.2) G8(2.4,-1.2) G9(3.2,-1.2) H1(-3.2,-2) H2(-2.4,-2) H3(-1.6,-2) H7(1.6,-2) H8(2.4,-2) H9(3.2,-2) J1(-3.2,-2.8) J2(-2.4,-2.8) J3(-1.6,-2.8) J7(1.6,-2.8) J8(2.4,-2.8) J9(3.2,-2.8) K1(-3.2,-3.6) K2(-2.4,-3.6) K3(-1.6,-3.6) K7(1.6,-3.6) K8(2.4,-3.6) K9(3.2,-3.6)
  silkscreen extent -4,-5 4,5
"LPC3240 HEAD" [mm]
  rect 1.2x1.2 hole 0.65: 1(0,0)
  round 1.2 hole 0.65: 2(0,-2) 3(2,0) 4(2,-2) 5(4,0) 6(4,-2) 7(6,0) 8(6,-2) 9(8,0) 10(8,-2) 11(10,0) 12(10,-2) 13(12,0) 14(12,-2) 15(14,0) 16(14,-2) 17(16,0) 18(16,-2) 19(18,0) 20(18,-2) 21(20,0) 22(20,-2) 23(22,0) 24(22,-2) 25(24,0) 26(24,-2) 27(26,0) 28(26,-2) 29(28,0) 30(28,-2) 31(30,0) 32(30,-2) 33(32,0) 34(32,-2) 35(34,0) 36(34,-2) 37(36,0) 38(36,-2) 39(38,0) 40(38,-2) 41(40,0) 42(40,-2) 43(42,0) 44(42,-2) 45(44,0) 46(44,-2) 47(46,0) 48(46,-2) 49(48,0) 50(48,-2)
  silkscreen extent -2.98,-3.6 49.24,1.95
SC70-5 [mm]
  rect 0.4x0.7 smd: 1(-0.65,-0.85) 2(0,-0.85) 3(0.65,-0.85) 4(0.65,0.85) 5(-0.65,0.85)
  silkscreen extent -1,-0.55 1,0.55
SMD-KEY [mm]
  rect 2x0.7 smd: 1(-3.7,2.25) 1(-3.7,-2.25) 2(3.7,2.25) 2(3.7,-2.25)
  silkscreen extent -3,-3 3,3
SOT23 [mm]
  rect 1x1.4 smd: 1(-0.95,-1.1) 2(0.95,-1.1) 3(0,1.1)
  silkscreen extent -1.42,-0.66 1.42,0.66
SOT143 [mm]
  rect 1.2x1.44 smd: 1(0.75,1.1)
  rect 1x1.44 smd: 2(-0.95,1.1) 3(-0.95,-1.1) 4(0.95,-1.1)
  silkscreen extent -1.45,-0.64 1.45,0.64
SOT1048-1 [mm]
  round 0.35 smd: A3(-5.184,6.78) A4(-4.387,6.78) A5(-3.589,6.78) A6(-2.791,6.78) A7(-1.994,6.78) A8(-1.196,6.78) A9(-0.399,6.78) A10(0.399,6.78) A11(1.196,6.78) A12(1.994,6.78) A13(2.791,6.78) A14(3.589,6.78) A15(4.387,6.78) A16(5.184,6.78) B2(-5.982,5.982) B3(-5.184,5.982) B4(-4.387,5.982) B5(-3.589,5.982) B6(-2.791,5.982) B7(-1.994,5.982) B8(-1.196,5.982) B9(-0.399,5.982) B10(0.399,5.982) B11(1.196,5.982) B12(1.994,5.982) B13(2.791,5.982) B14(3.589,5.982) B15(4.387,5.982) B16(5.184,5.982) B17(5.982,5.982) C1(-6.779,5.184) C2(-5.982,5.184) C3(-5.184,5.184) C4(-4.387,5.184) C5(-3.589,5.184) C6(-2.791,5.184) C7(-1.994,5.184) C8(-1.196,5.184) C9(-0.399,5.184) C10(0.399,5.184) C11(1.196,5.184) C12(1.994,5.184) C13(2.791,5.184) C14(3.589,5.184) C15(4.387,5.184) C16(5.184,5.184) C17(5.982,5.184) C18(6.779,5.184) D1(-6.779,4.387) D2(-5.982,4.387) D3(-5.184,4.387) D4(-4.387,4.387) D5(-3.589,4.387) D6(-2.791,4.387) D7(-1.994,4.387) D8(-1.196,4.387) D9(-0.399,4.387) D10(0.399,4.387) D11(1.196,4.387) D12(1.994,4.387) D13(2.791,4.387) D14(3.589,4.387) D15(4.387,4.387) D16(5.184,4.387) D17(5.982,4.387) D18(6.779,4.387) E1(-6.779,3.589) E2(-5.982,3.589) E3(-5.184,3.589) E4(-4.387,3.589) E5(-3.589,3.589) E6(-2.791,3.589) E7(-1.994,3.589) E8(-1.196,3.589) E9(-0.399,3.589) E10(0.399,3.589) E11(1.196,3.589) E12(1.994,3.589) E13(2.791,3.589) E14(3.589,3.589) E15(4.387,3.589) E16(5.184,3.589) E17(5.982,3.589) E18(6.779,3.589) F1(-6.779,2.792) F2(-5.982,2.792) F3(-5.184,2.792) F4(-4.387,2.792) F5(-3.589,2.792) F6(-2.791,2.792) F7(-1.994,2.792) F8(-1.196,2.792) F9(-0.399,2.792) F10(0.399,2.792) F11(1.196,2.792) F12(1.994,2.792) F13(2.791,2.792) F14(3.589,2.792) F15(4.387,2.792) F16(5.184,2.792) F17(5.982,2.792) F18(6.779,2.792) G1(-6.779,1.994) G2(-5.982,1.994) G3(-5.184,1.994) G4(-4.387,1.994) G5(-3.589,1.994) G6(-2.791,1.994) G7(-1.994,1.994) G8(-1.196,1.994) G9(-0.399,1.994) G10(0.399,1.994) G11(1.196,1.994) G12(1.994,1.994) G13(2.791,1.994) G14(3.589,1.994) G15(4.387,1.994) G16(5.184,1.994) G17(5.982,1.994) G18(6.779,1.994) H1(-6.779,1.197) H2(-5.982,1.197) H3(-5.184,1.197) H4(-4.387,1.197) H5(-3.589,1.197) H6(-2.791,1.197) H7(-1.994,1.197) H12(1.994,1.197) H13(2.791,1.197) H14(3.589,1.197) H15(4.387,1.197) H16(5.184,1.197) H17(5.982,1.197) H18(6.779,1.197) J1(-6.779,0.399) J2(-5.982,0.399) J3(-5.184,0.399) J4(-4.387,0.399) J5(-3.589,0.399) J6(-2.791,0.399) J7(-1.994,0.399) J12(1.994,0.399) J13(2.791,0.399) J14(3.589,0.399) J15(4.387,0.399) J16(5.184,0.399) J17(5.982,0.399) J18(6.779,0.399) K1(-6.779,-0.399) K2(-5.982,-0.399) K3(-5.184,-0.399) K4(-4.387,-0.399) K5(-3.589,-0.399) K6(-2.791,-0.399) K7(-1.994,-0.399) K12(1.994,-0.399) K13(2.791,-0.399) K14(3.589,-0.399) K15(4.387,-0.399) K16(5.184,-0.399) K17(5.982,-0.399) K18(6.779,-0.399) L1(-6.779,-1.196) L2(-5.982,-1.196) L3(-5.184,-1.196) L4(-4.387,-1.196) L5(-3.589,-1.196) L6(-2.791,-1.196) L7(-1.994,-1.196) L12(1.994,-1.196) L13(2.791,-1.196) L14(3.589,-1.196) L15(4.387,-1.196) L16(5.184,-1.196) L17(5.982,-1.196) L18(6.779,-1.196) M1(-6.779,-1.994) M2(-5.982,-1.994) M3(-5.184,-1.994) M4(-4.387,-1.994) M5(-3.589,-1.994) M6(-2.791,-1.994) M7(-1.994,-1.994) M8(-1.196,-1.994) M9(-0.399,-1.994) M10(0.399,-1.994) M11(1.196,-1.994) M12(1.994,-1.994) M13(2.791,-1.994) M14(3.589,-1.994) M15(4.387,-1.994) M16(5.184,-1.994) M17(5.982,-1.994) M18(6.779,-1.994) N1(-6.779,-2.791) N2(-5.982,-2.791) N3(-5.184,-2.791) N4(-4.387,-2.791) N5(-3.589,-2.791) N6(-2.791,-2.791) N7(-1.994,-2.791) N8(-1.196,-2.791) N9(-0.399,-2.791) N10(0.399,-2.791) N11(1.196,-2.791) N12(1.994,-2.791) N13(2.791,-2.791) N14(3.589,-2.791) N15(4.387,-2.791) N16(5.184,-2.791) N17(5.982,-2.791) N18(6.779,-2.791) P1(-6.779,-3.589) P2(-5.982,-3.589) P3(-5.184,-3.589) P4(-4.387,-3.589) P5(-3.589,-3.589) P6(-2.791,-3.589) P7(-1.994,-3.589) P8(-1.196,-3.589) P9(-0.399,-3.589) P10(0.399,-3.589) P11(1.196,-3.589) P12(1.994,-3.589) P13(2.791,-3.589) P14(3.589,-3.589) P15(4.387,-3.589) P16(5.184,-3.589) P17(5.982,-3.589) P18(6.779,-3.589) R1(-6.779,-4.386) R2(-5.982,-4.386) R3(-5.184,-4.386) R4(-4.387,-4.386) R5(-3.589,-4.386) R6(-2.791,-4.386) R7(-1.994,-4.386) R8(-1.196,-4.386) R9(-0.399,-4.386) R10(0.399,-4.386) R11(1.196,-4.386) R12(1.994,-4.386) R13(2.791,-4.386) R14(3.589,-4.386) R15(4.387,-4.386) R16(5.184,-4.386) R17(5.982,-4.386) R18(6.779,-4.386) T1(-6.779,-5.184) T2(-5.982,-5.184) T3(-5.184,-5.184) T4(-4.387,-5.184) T5(-3.589,-5.184) T6(-2.791,-5.184) T7(-1.994,-5.184) T8(-1.196,-5.184) T9(-0.399,-5.184) T10(0.399,-5.184) T11(1.196,-5.184) T12(1.994,-5.184) T13(2.791,-5.184) T14(3.589,-5.184) T15(4.387,-5.184) T16(5.184,-5.184) T17(5.982,-5.184) T18(6.779,-5.184) U2(-5.982,-5.982) U3(-5.184,-5.982) U4(-4.387,-5.982) U5(-3.589,-5.982) U6(-2.791,-5.982) U7(-1.994,-5.982) U8(-1.196,-5.982) U9(-0.399,-5.982) U10(0.399,-5.982) U11(1.196,-5.982) U12(1.994,-5.982) U13(2.791,-5.982) U14(3.589,-5.982) U15(4.387,-5.982) U16(5.184,-5.982) U17(5.982,-5.982) V3(-5.184,-6.779) V4(-4.387,-6.779) V5(-3.589,-6.779) V6(-2.791,-6.779) V7(-1.994,-6.779) V8(-1.196,-6.779) V9(-0.399,-6.779) V10(0.399,-6.779) V11(1.196,-6.779) V12(1.994,-6.779) V13(2.791,-6.779) V14(3.589,-6.779) V15(4.387,-6.779) V16(5.184,-6.779)
  silkscreen extent -7.62,-7.58 7.58,7.62
TP06SQ [mil]
  rect 23.61x23.61 smd: TP(0,0)
TSOP48 [mm]
  rect 1.1x0.3 smd: 1(-9.625,5.75) 2(-9.625,5.25) 3(-9.625,4.75) 4(-9.625,4.25) 5(-9.625,3.75) 6(-9.625,3.25) 7(-9.625,2.75) 8(-9.625,2.25) 9(-9.625,1.75) 10(-9.625,1.25) 11(-9.625,0.75) 12(-9.625,0.25) 13(-9.625,-0.25) 14(-9.625,-0.75) 15(-9.625,-1.25) 16(-9.625,-1.75) 17(-9.625,-2.25) 18(-9.625,-2.75) 19(-9.625,-3.25) 20(-9.625,-3.75) 21(-9.625,-4.25) 22(-9.625,-4.75) 23(-9.625,-5.25) 24(-9.625,-5.75) 25(9.625,-5.75) 26(9.625,-5.25) 27(9.625,-4.75) 28(9.625,-4.25) 29(9.625,-3.75) 30(9.625,-3.25) 31(9.625,-2.75) 32(9.625,-2.25) 33(9.625,-1.75) 34(9.625,-1.25) 35(9.625,-0.75) 36(9.625,-0.25) 37(9.625,0.25) 38(9.625,0.75) 39(9.625,1.25) 40(9.625,1.75) 41(9.625,2.25) 42(9.625,2.75) 43(9.625,3.25) 44(9.625,3.75) 45(9.625,4.25) 46(9.625,4.75) 47(9.625,5.25) 48(9.625,5.75)
  silkscreen extent -11.24,-6 9.15,6.12
TSSOP8 [mm]
  rect 0.35x1.2 smd: 1(-0.975,-2.925) 2(-0.325,-2.925) 3(0.325,-2.925) 4(0.975,-2.925) 5(0.975,2.925) 6(0.325,2.925) 7(-0.325,2.925) 8(-0.975,2.925)
  silkscreen extent -2.08,-3.35 1.4,2.15
XTAL2 [mm]
  rect 1x1.8 smd: 1(-1.19,0) 2(1.31,0)
  silkscreen extent -1.91,-0.91 2.03,0.91
XTAL4 [mm]
  rect 1.4x1.15 smd: 1(-1.6,-0.8) 2(0.6,-0.8) 3(0.6,0.8) 4(-1.6,0.8)
  silkscreen extent -3.1,-1.7 1.4,1.5

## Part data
1 2 3 4 5 6 7 8 9 10 11 12 13 14 15 16 A1 A2 A3 A4 A5 A6 A7 A8 A9 A10 A11 A12 A13 A14 A15: library part TP0.5
C1 C2 C4 C5 C6 C7 C8 C9 C10 C13 C14 C15 C16 C17 C18 C19 C20 C21 C22 C23 C24 C25 C26 C27 C28 C29 C30 C31 C32 C33 C34 C35 C36 C37 C38 C39 C40 C41 C43 C44 C45 C46 C47 C48 C49 C50 C51 C52 C53 C54 C55 C57 C58 C59 C60 C61 C62 C63 C65: library part C-EUC0402
C3: library part C-TRIMMCTZ3
C11 C12 C42 C56 C64: library part C-EUC0805
D1 D2: library part BAS16
IC1: library part H27U1G8F2BTR
IC3: library part LPC32X0
IC4 IC7 IC8: library part 74LVC1G125DCK
IC5: library part CAT811S
L1 L2: library part L_0603
Q1: library part RTCCRYSTAL
Q2: library part CRYSTAL4
R1 R2 R3 R4 R5 R6 R7 R8 R9 R10 R11 R12 R13 R14 R15 R16 R17 R18 R19 R20 R21 R22 R23 R24 R25 R26 R27 R28 R29 R30 R31 R32 R33 R34 R35 R36 R37 R38 R39 R40 R41 R42 R43 R44 R45 R46 R47: library part R-EU_R0402
RN1 RN2: library part 4R-NEXB18V
SP1 SP2 SP3 SP4 SP5 SP6: library part TPTP06SQ
TC1 TC2: library part TPB1,27

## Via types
v1: diameter 16, hole 8, TOP to BOTTOM, tented both sides, 541 vias

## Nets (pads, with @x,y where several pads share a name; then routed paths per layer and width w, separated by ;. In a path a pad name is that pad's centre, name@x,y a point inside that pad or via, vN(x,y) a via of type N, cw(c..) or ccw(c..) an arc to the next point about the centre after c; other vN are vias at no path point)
pads on no net: 1.TP 2.TP 3.TP 4.TP 5.TP 6.TP 7.TP 8.TP 9.TP 10.TP 11.TP 12.TP 13.TP 14.TP 15.TP 16.TP A1.TP A2.TP A3.TP A4.TP A5.TP A6.TP A7.TP A8.TP A9.TP A10.TP A11.TP A12.TP A13.TP A14.TP A15.TP C1.1 C1.2 C2.1 C2.2 C3.1 C3.2 C4.1 C4.2 C5.1 C5.2 C6.1 C6.2 C7.1 C7.2 C8.1 C8.2 C9.1 C9.2 C10.1 C10.2 C11.1 C11.2 C12.1 C12.2 C13.1 C13.2 C14.1 C14.2 C15.1 C15.2 C16.1 C16.2 C17.1 C17.2 C18.1 C18.2 C19.1 C19.2 C20.1 C20.2 C21.1 C21.2 C22.1 C22.2 C23.1 C23.2 C24.1 C24.2 C25.1 C25.2 C26.1 C26.2 C27.1 C27.2 C28.1 C28.2 C29.1 C29.2 C30.1 C30.2 C31.1 C31.2 C32.1 C32.2 C33.1 C33.2 C34.1 C34.2 C35.1 C35.2 C36.1 C36.2 C37.1 C37.2 C38.1 C38.2 C39.1 C39.2 C40.1 C40.2 C41.1 C41.2 C42.1 C42.2 C43.1 C43.2 C44.1 C44.2 C45.1 C45.2 C46.1 C46.2 C47.1 C47.2 C48.1 C48.2 C49.1 C49.2 C50.1 C50.2 C51.1 C51.2 C52.1 C52.2 C53.1 C53.2 C54.1 C54.2 C55.1 C55.2 C56.1 C56.2 C57.1 C57.2 C58.1 C58.2 C59.1 C59.2 C60.1 C60.2 C61.1 C61.2 C62.1 C62.2 C63.1 C63.2 C64.1 C64.2 C65.1 C65.2 D1.1 D1.2 D1.3 D2.1 D2.2 D2.3 IC1.1 IC1.2 IC1.3 IC1.4 IC1.5 IC1.6 IC1.7 IC1.8 IC1.9 IC1.10 IC1.11 IC1.12 IC1.13 IC1.14 IC1.15 IC1.16 IC1.17 IC1.18 IC1.19 IC1.20 IC1.21 IC1.22 IC1.23 IC1.24 IC1.25 IC1.26 IC1.27 IC1.28 IC1.29 IC1.30 IC1.31 IC1.32 IC1.33 IC1.34 IC1.35 IC1.36 IC1.37 IC1.38 IC1.39 IC1.40 IC1.41 IC1.42 IC1.43 IC1.44 IC1.45 IC1.46 IC1.47 IC1.48 IC2.1 IC2.2 IC2.3 IC2.4 IC2.5 IC2.6 IC2.7 IC2.8 IC3.A3 IC3.A4 IC3.A5 IC3.A6 IC3.A7 IC3.A8 IC3.A9 IC3.A10 IC3.A11 IC3.A12 IC3.A13 IC3.A14 IC3.A15 IC3.A16 IC3.B2 IC3.B3 IC3.B4 IC3.B5 IC3.B6 IC3.B7 IC3.B8 IC3.B9 IC3.B10 IC3.B11 IC3.B12 IC3.B13 IC3.B14 IC3.B15 IC3.B16 IC3.B17 IC3.C1 IC3.C2 IC3.C3 IC3.C4 IC3.C5 IC3.C6 IC3.C7 IC3.C8 IC3.C9 IC3.C10 IC3.C11 IC3.C12 IC3.C13 IC3.C14 IC3.C15 IC3.C16 IC3.C17 IC3.C18 IC3.D1 IC3.D2 IC3.D3 IC3.D4 IC3.D5 IC3.D6 IC3.D7 IC3.D8 IC3.D9 IC3.D10 IC3.D11 IC3.D12 IC3.D13 IC3.D14 IC3.D15 IC3.D16 IC3.D17 IC3.D18 IC3.E1 IC3.E2 IC3.E3 IC3.E4 IC3.E5 IC3.E6 IC3.E7 IC3.E8 IC3.E9 IC3.E10 IC3.E11 IC3.E12 IC3.E13 IC3.E14 IC3.E15 IC3.E16 IC3.E17 IC3.E18 IC3.F1 IC3.F2 IC3.F3 IC3.F4 IC3.F5 IC3.F6 IC3.F7 IC3.F8 IC3.F9 IC3.F10 IC3.F11 IC3.F12 IC3.F13 IC3.F14 IC3.F15 IC3.F16 IC3.F17 IC3.F18 IC3.G1 IC3.G2 IC3.G3 IC3.G4 IC3.G5 IC3.G6 IC3.G7 IC3.G8 IC3.G9 IC3.G10 IC3.G11 IC3.G12 IC3.G13 IC3.G14 IC3.G15 IC3.G16 IC3.G17 IC3.G18 IC3.H1 IC3.H2 IC3.H3 IC3.H4 IC3.H5 IC3.H6 IC3.H7 IC3.H12 IC3.H13 IC3.H14 IC3.H15 IC3.H16 IC3.H17 IC3.H18 IC3.J1 IC3.J2 IC3.J3 IC3.J4 IC3.J5 IC3.J6 IC3.J7 IC3.J12 IC3.J13 IC3.J14 IC3.J15 IC3.J16 IC3.J17 IC3.J18 IC3.K1 IC3.K2 IC3.K3 IC3.K4 IC3.K5 IC3.K6 IC3.K7 IC3.K12 IC3.K13 IC3.K14 IC3.K15 IC3.K16 IC3.K17 IC3.K18 IC3.L1 IC3.L2 IC3.L3 IC3.L4 IC3.L5 IC3.L6 IC3.L7 IC3.L12 IC3.L13 IC3.L14 IC3.L15 IC3.L16 IC3.L17 IC3.L18 IC3.M1 IC3.M2 IC3.M3 IC3.M4 IC3.M5 IC3.M6 IC3.M7 IC3.M8 IC3.M9 IC3.M10 IC3.M11 IC3.M12 IC3.M13 IC3.M14 IC3.M15 IC3.M16 IC3.M17 IC3.M18 IC3.N1 IC3.N2 IC3.N3 IC3.N4 IC3.N5 IC3.N6 IC3.N7 IC3.N8 IC3.N9 IC3.N10 IC3.N11 IC3.N12 IC3.N13 IC3.N14 IC3.N15 IC3.N16 IC3.N17 IC3.N18 IC3.P1 IC3.P2 IC3.P3 IC3.P4 IC3.P5 IC3.P6 IC3.P7 IC3.P8 IC3.P9 IC3.P10 IC3.P11 IC3.P12 IC3.P13 IC3.P14 IC3.P15 IC3.P16 IC3.P17 IC3.P18 IC3.R1 IC3.R2 IC3.R3 IC3.R4 IC3.R5 IC3.R6 IC3.R7 IC3.R8 IC3.R9 IC3.R10 IC3.R11 IC3.R12 IC3.R13 IC3.R14 IC3.R15 IC3.R16 IC3.R17 IC3.R18 IC3.T1 IC3.T2 IC3.T3 IC3.T4 IC3.T5 IC3.T6 IC3.T7 IC3.T8 IC3.T9 IC3.T10 IC3.T11 IC3.T12 IC3.T13 IC3.T14 IC3.T15 IC3.T16 IC3.T17 IC3.T18 IC3.U2 IC3.U3 IC3.U4 IC3.U5 IC3.U6 IC3.U7 IC3.U8 IC3.U9 IC3.U10 IC3.U11 IC3.U12 IC3.U13 IC3.U14 IC3.U15 IC3.U16 IC3.U17 IC3.V3 IC3.V4 IC3.V5 IC3.V6 IC3.V7 IC3.V8 IC3.V9 IC3.V10 IC3.V11 IC3.V12 IC3.V13 IC3.V14 IC3.V15 IC3.V16 IC4.1 IC4.2 IC4.3 IC4.4 IC4.5 IC5.1 IC5.2 IC5.3 IC5.4 IC6.A1 IC6.A2 IC6.A3 IC6.A7 IC6.A8 IC6.A9 IC6.B1 IC6.B2 IC6.B3 IC6.B7 IC6.B8 IC6.B9 IC6.C1 IC6.C2 IC6.C3 IC6.C7 IC6.C8 IC6.C9 IC6.D1 IC6.D2 IC6.D3 IC6.D7 IC6.D8 IC6.D9 IC6.E1 IC6.E2 IC6.E3 IC6.E7 IC6.E8 IC6.E9 IC6.F1 IC6.F2 IC6.F3 IC6.F7 IC6.F8 IC6.F9 IC6.G1 IC6.G2 IC6.G3 IC6.G7 IC6.G8 IC6.G9 IC6.H1 IC6.H2 IC6.H3 IC6.H7 IC6.H8 IC6.H9 IC6.J1 IC6.J2 IC6.J3 IC6.J7 IC6.J8 IC6.J9 IC6.K1 IC6.K2 IC6.K3 IC6.K7 IC6.K8 IC6.K9 IC7.1 IC7.2 IC7.3 IC7.4 IC7.5 IC8.1 IC8.2 IC8.3 IC8.4 IC8.5 J1.1 J1.2 J1.3 J1.4 J1.5 J1.6 J1.7 J1.8 J1.9 J1.10 J1.11 J1.12 J1.13 J1.14 J1.15 J1.16 J1.17 J1.18 J1.19 J1.20 J1.21 J1.22 J1.23 J1.24 J1.25 J1.26 J1.27 J1.28 J1.29 J1.30 J1.31 J1.32 J1.33 J1.34 J1.35 J1.36 J1.37 J1.38 J1.39 J1.40 J1.41 J1.42 J1.43 J1.44 J1.45 J1.46 J1.47 J1.48 J1.49 J1.50 J2.1 J2.2 J2.3 J2.4 J2.5 J2.6 J2.7 J2.8 J2.9 J2.10 J2.11 J2.12 J2.13 J2.14 J2.15 J2.16 J2.17 J2.18 J2.19 J2.20 J2.21 J2.22 J2.23 J2.24 J2.25 J2.26 J2.27 J2.28 J2.29 J2.30 J2.31 J2.32 J2.33 J2.34 J2.35 J2.36 J2.37 J2.38 J2.39 J2.40 J2.41 J2.42 J2.43 J2.44 J2.45 J2.46 J2.47 J2.48 J2.49 J2.50 L1.1 L1.2 L2.1 L2.2 LED1.A LED1.C LED2.A LED2.C Q1.1 Q1.2 Q2.1 Q2.2 Q2.3 Q2.4 R1.1 R1.2 R2.1 R2.2 R3.1 R3.2 R4.1 R4.2 R5.1 R5.2 R6.1 R6.2 R7.1 R7.2 R8.1 R8.2 R9.1 R9.2 R10.1 R10.2 R11.1 R11.2 R12.1 R12.2 R13.1 R13.2 R14.1 R14.2 R15.1 R15.2 R16.1 R16.2 R17.1 R17.2 R18.1 R18.2 R19.1 R19.2 R20.1 R20.2 R21.1 R21.2 R22.1 R22.2 R23.1 R23.2 R24.1 R24.2 R25.1 R25.2 R26.1 R26.2 R27.1 R27.2 R28.1 R28.2 R29.1 R29.2 R30.1 R30.2 R31.1 R31.2 R32.1 R32.2 R33.1 R33.2 R34.1 R34.2 R35.1 R35.2 R36.1 R36.2 R37.1 R37.2 R38.1 R38.2 R39.1 R39.2 R40.1 R40.2 R41.1 R41.2 R42.1 R42.2 R43.1 R43.2 R44.1 R44.2 R45.1 R45.2 R46.1 R46.2 R47.1 R47.2 RESET1.1 RESET1.2 RN1.1 RN1.2 RN1.3 RN1.4 RN1.5 RN1.6 RN1.7 RN1.8 RN2.1 RN2.2 RN2.3 RN2.4 RN2.5 RN2.6 RN2.7 RN2.8 SP1.TP SP2.TP SP3.TP SP4.TP SP5.TP SP6.TP TC1.TP TC2.TP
